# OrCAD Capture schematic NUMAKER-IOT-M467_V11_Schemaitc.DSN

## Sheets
1 Nu-Link2-Me: size A3; title: Nu-Link2-Me; rev: 1.0; company: CMHuang; note: Nu-Link2-Me
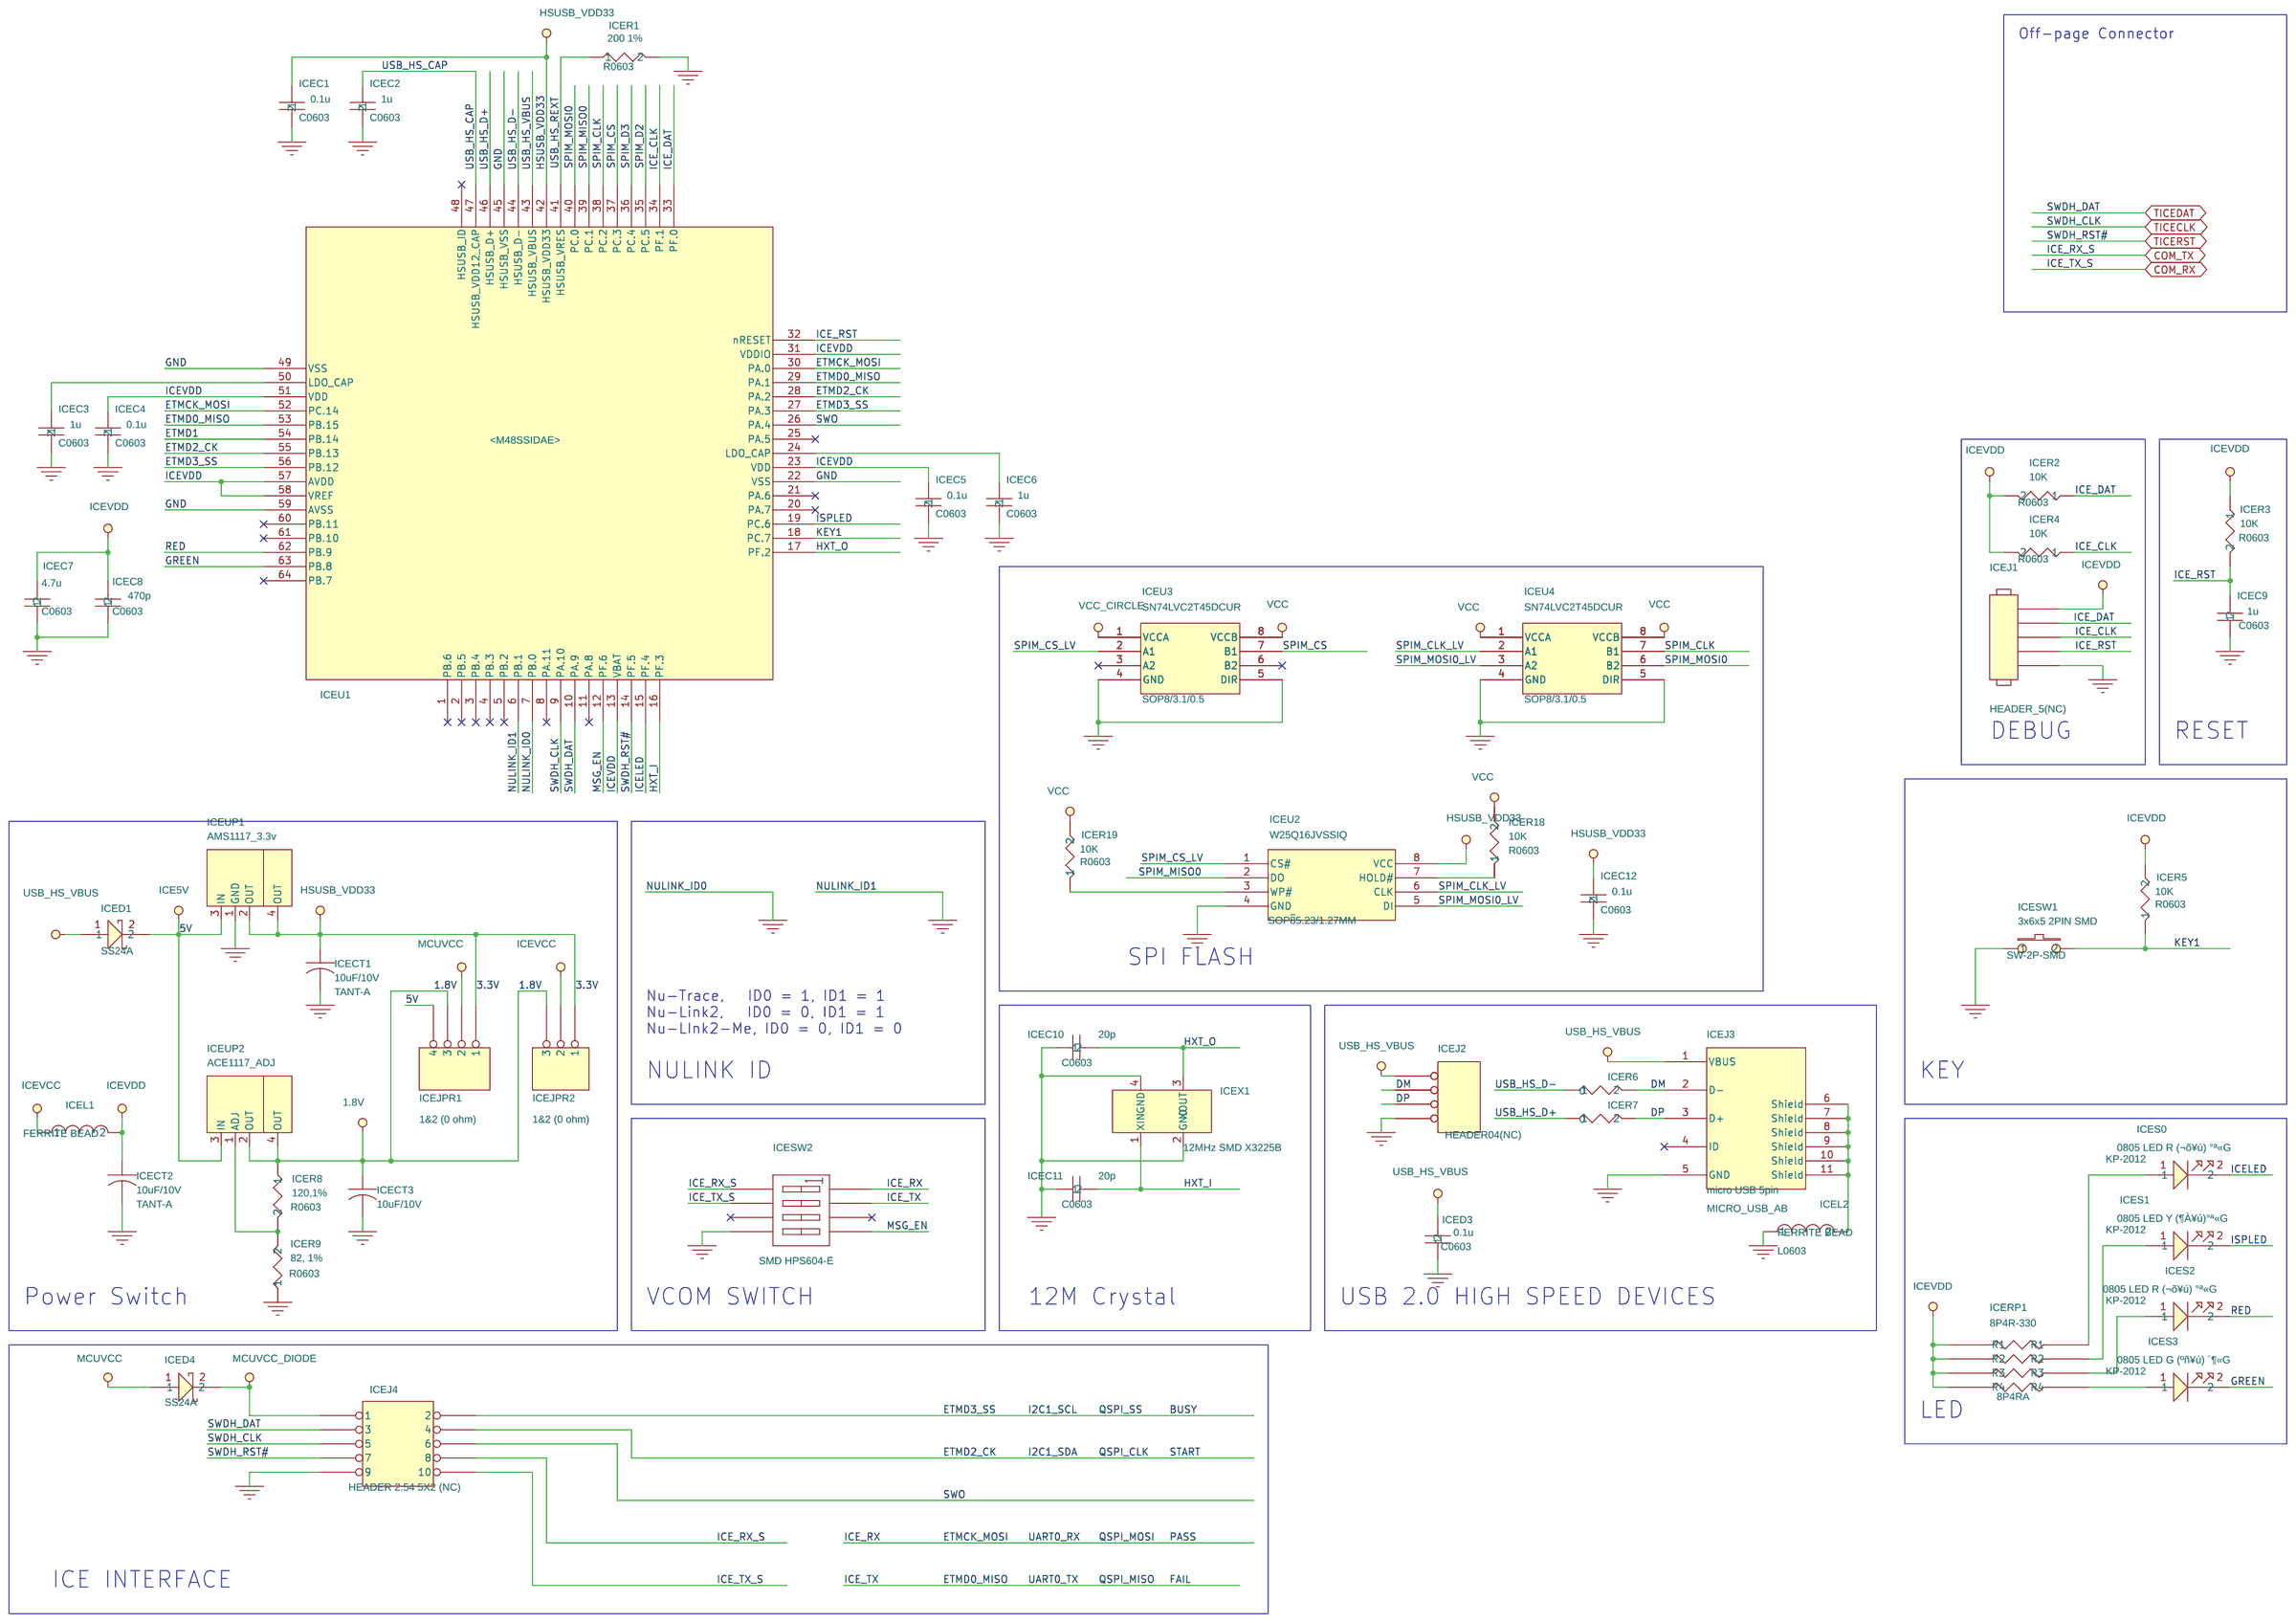
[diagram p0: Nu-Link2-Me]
2 Power Source: size A; title: Power Source; rev: r1.0; note: NuMaker-IoT-M467
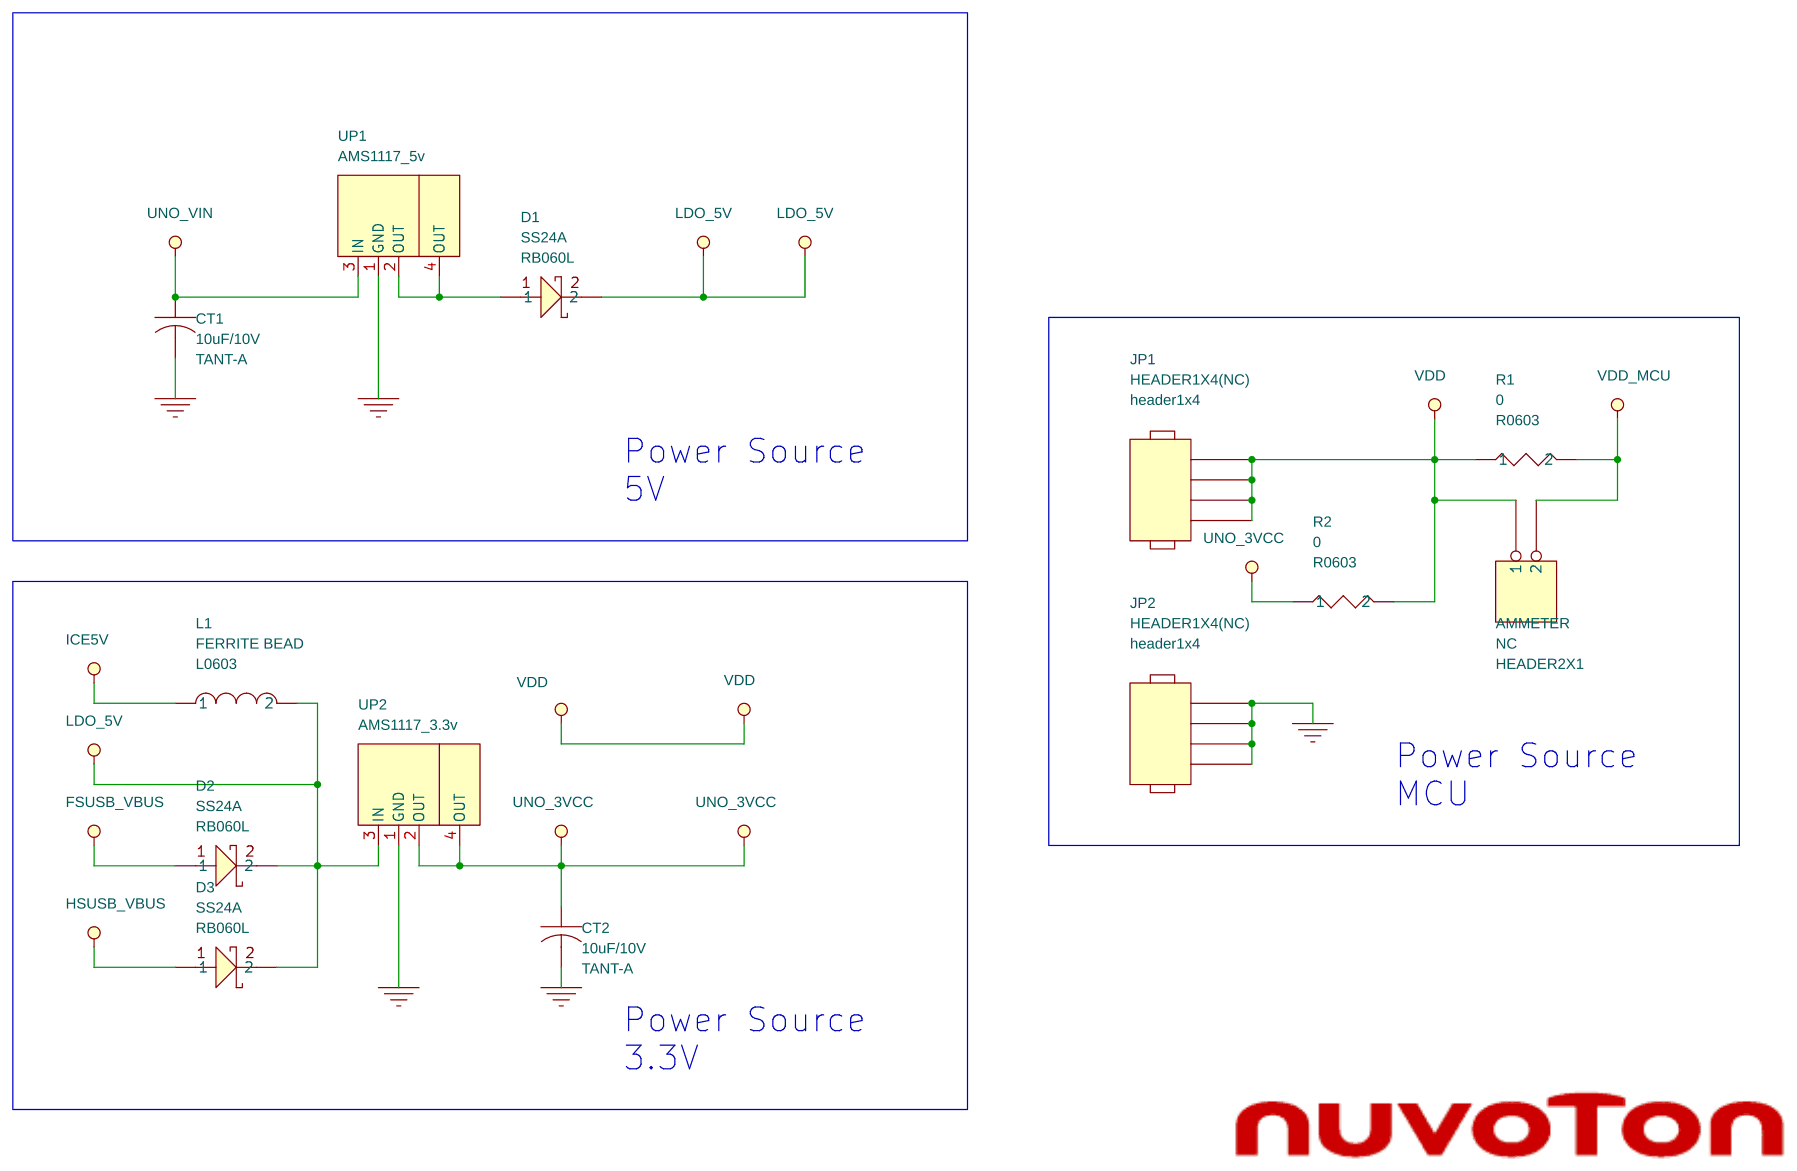
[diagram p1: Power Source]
3 M460_LQFP176: size C; title: M460_LQFP176; rev: r1.1; note: NuMaker-IoT-M467
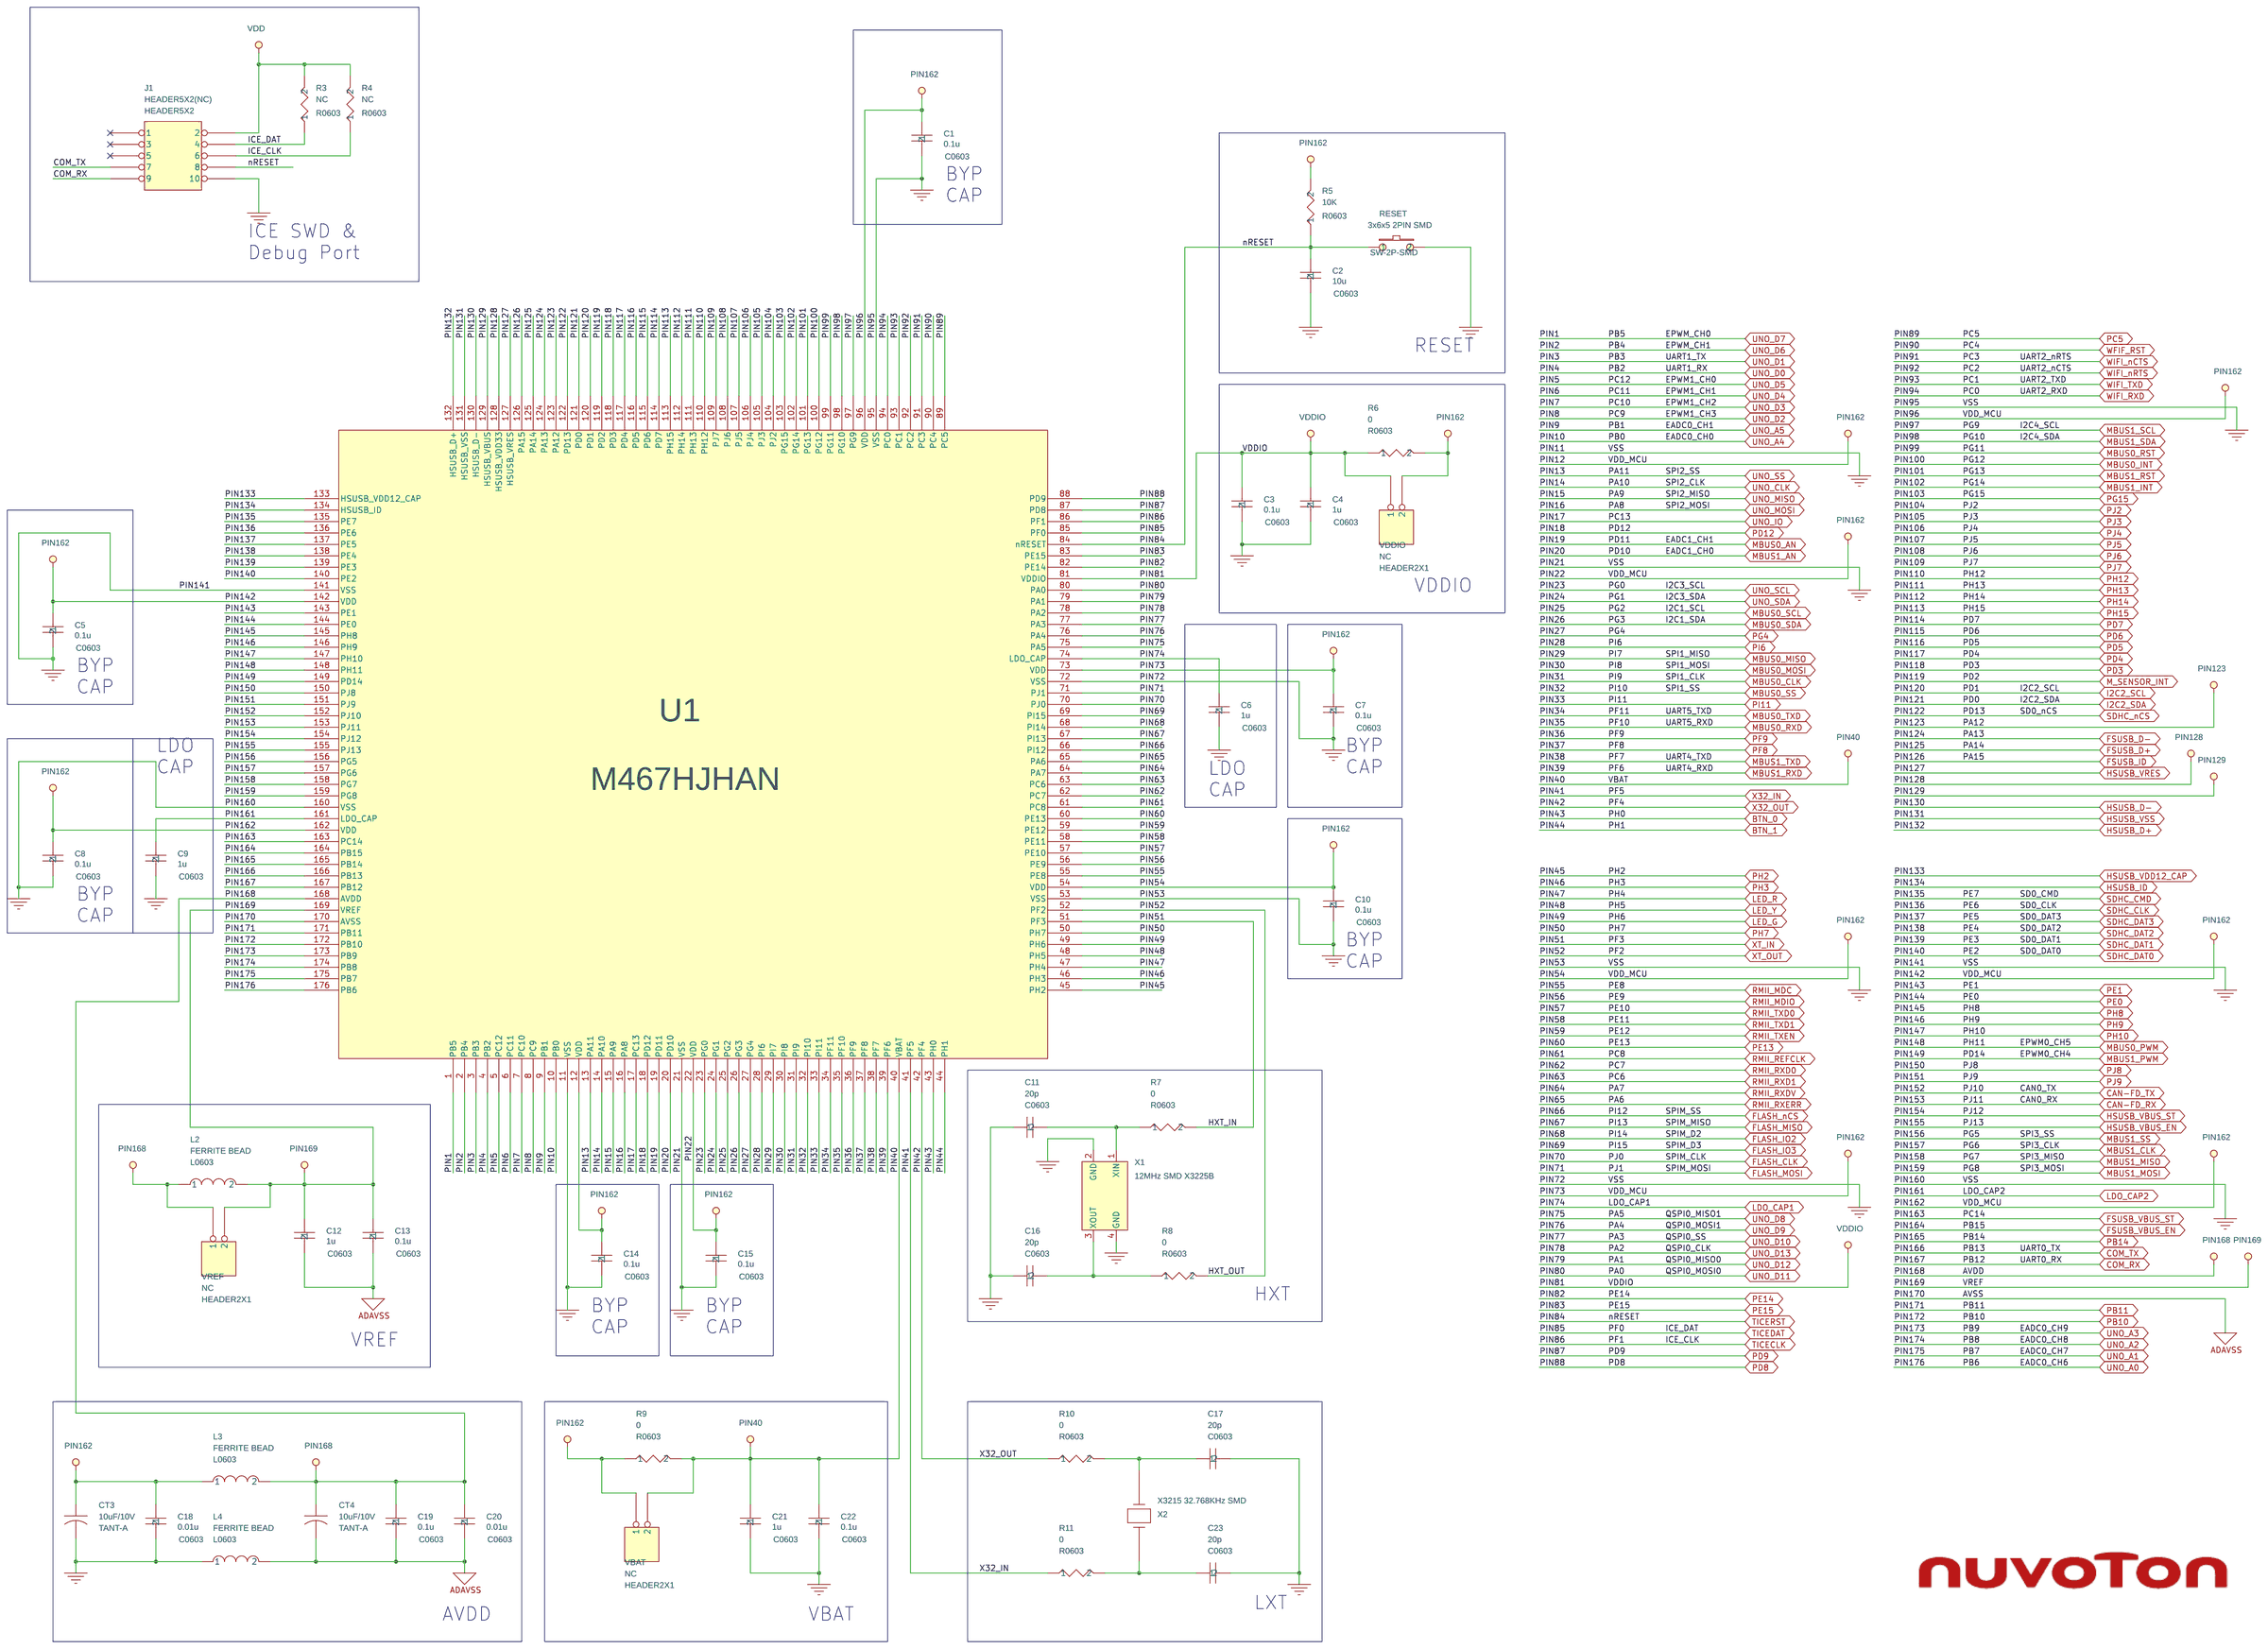
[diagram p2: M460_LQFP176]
4 SPI Flash: size A; title: SPI Flash; rev: r1.0; note: NuMaker-IoT-M467
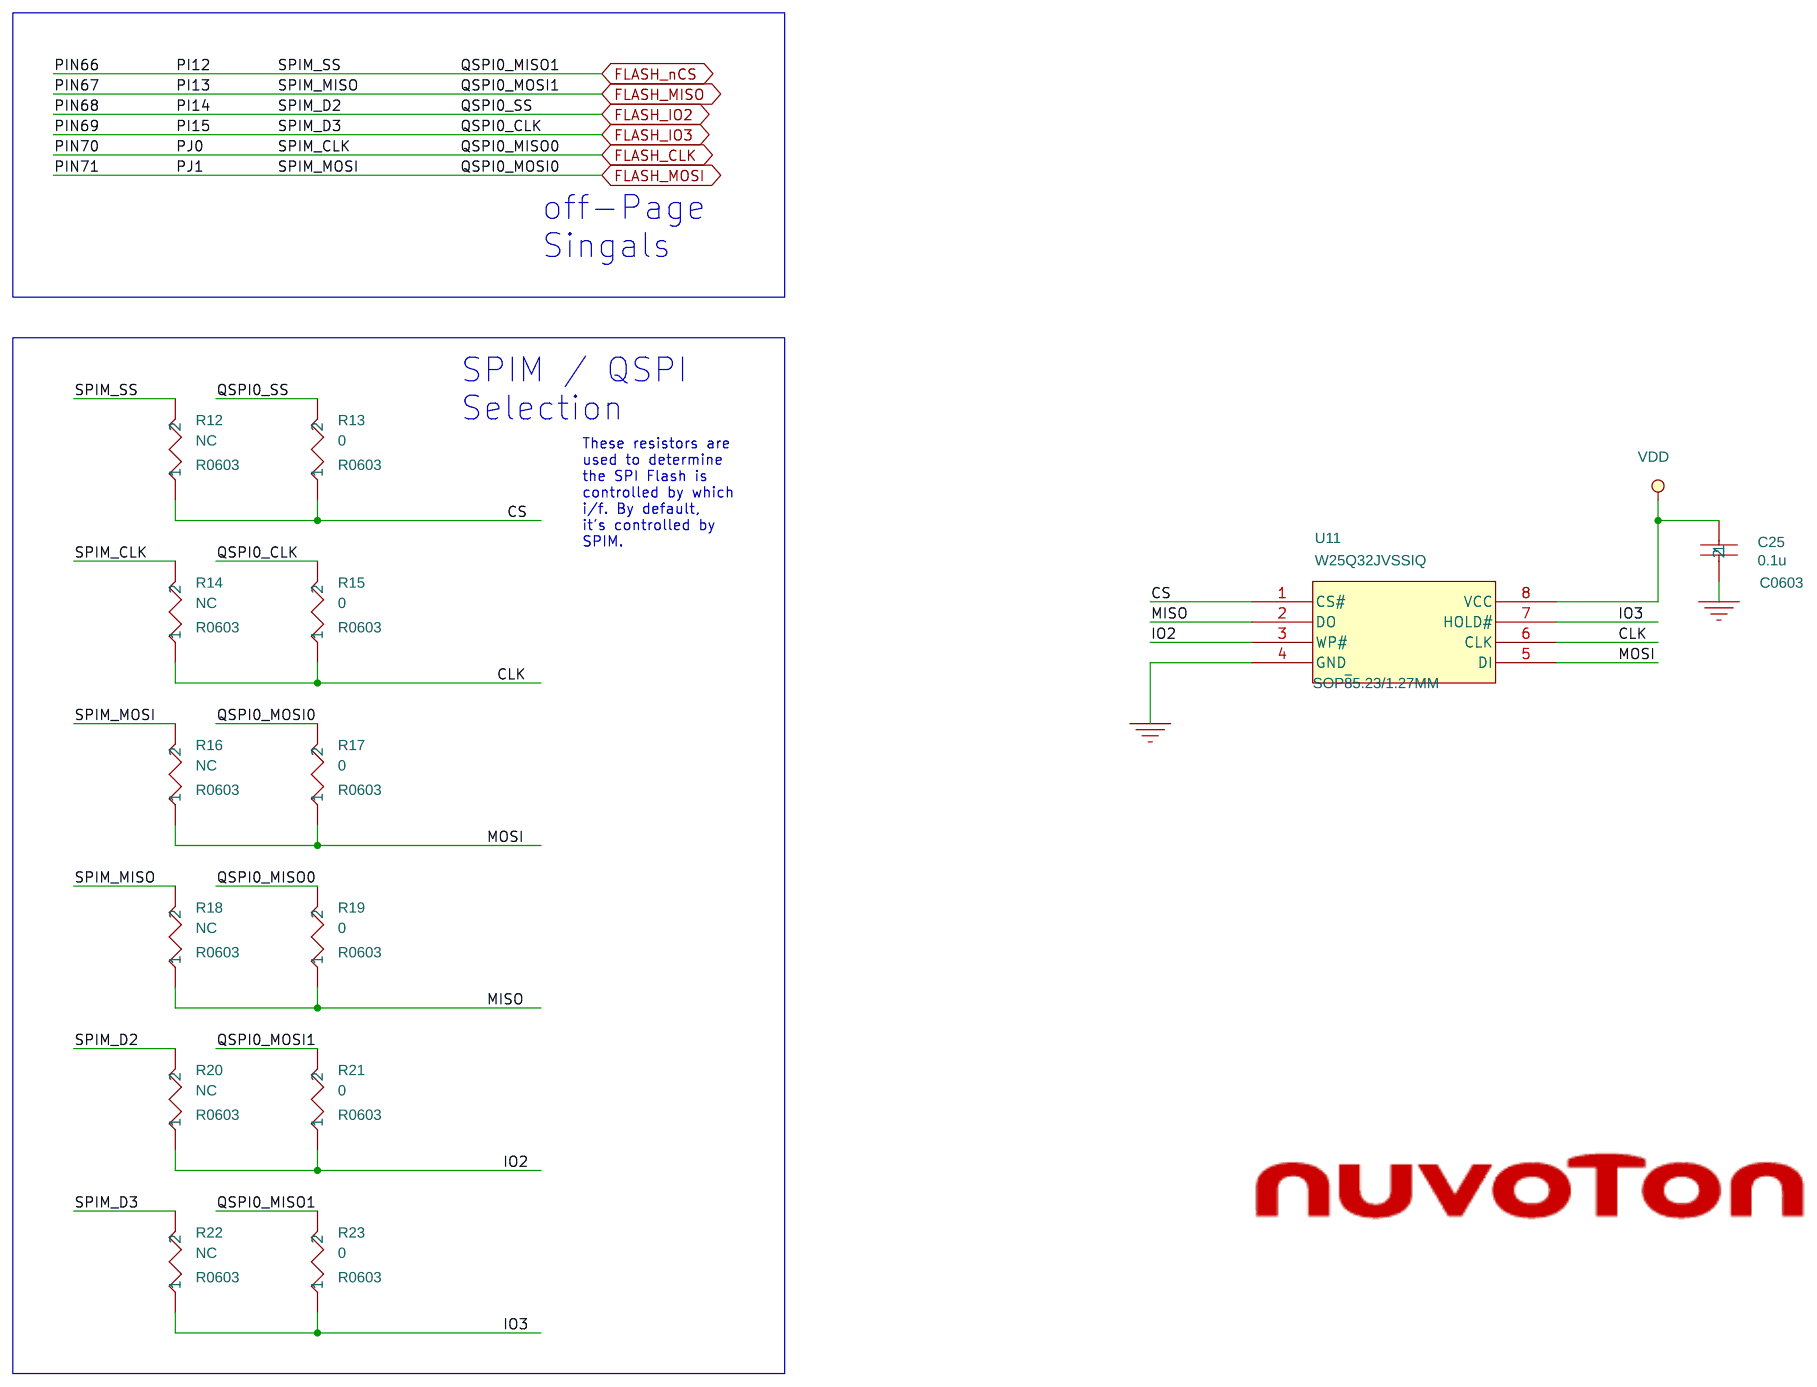
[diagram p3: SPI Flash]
5 FS-USB: size A; title: FS-USB; rev: r1.0; note: NuMaker-IoT-M467
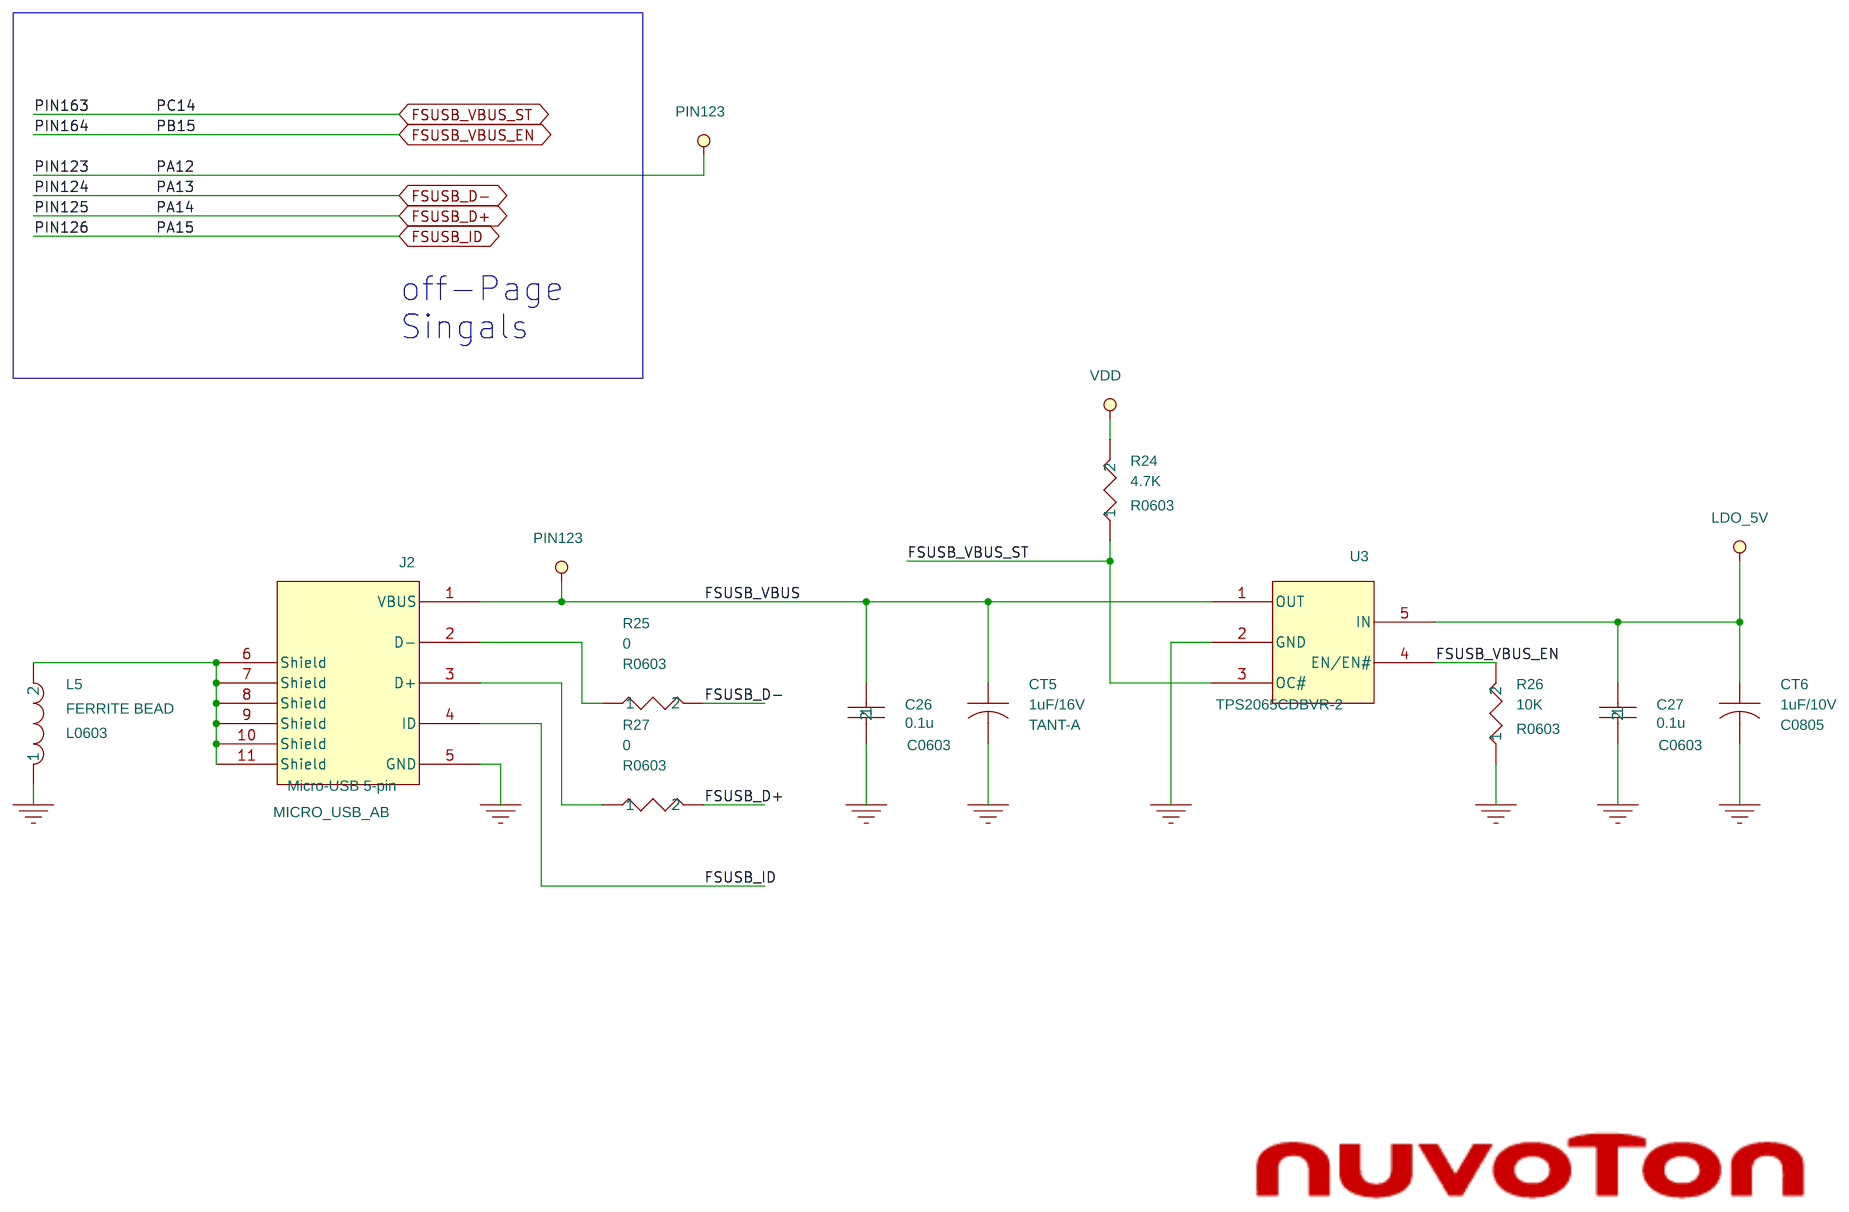
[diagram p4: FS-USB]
6 HS-USB: size A; title: HS-USB; rev: r1.0; note: NuMaker-IoT-M467
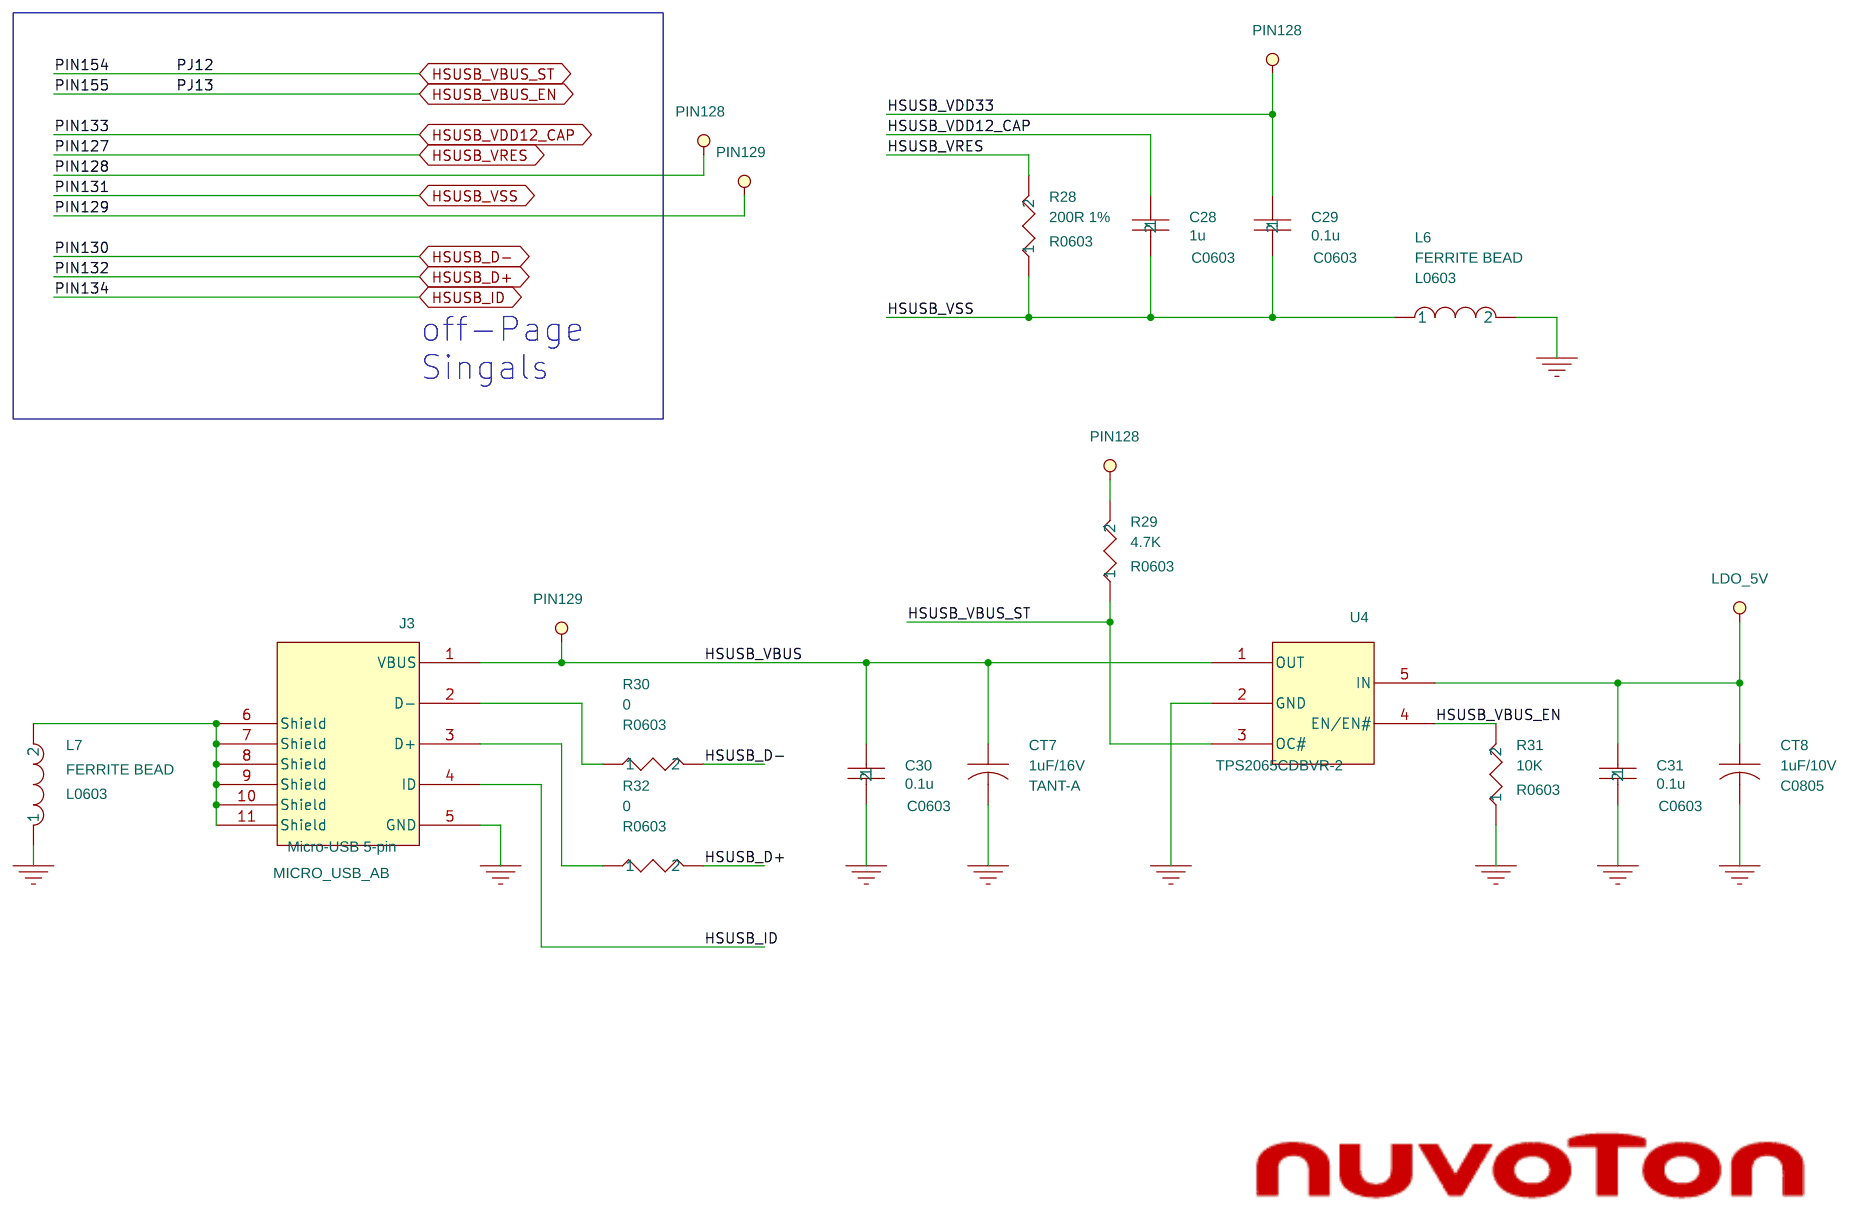
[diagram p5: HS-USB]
7 SD Card: size A; title: SD Card; rev: r1.0; note: NuMaker-IoT-M467
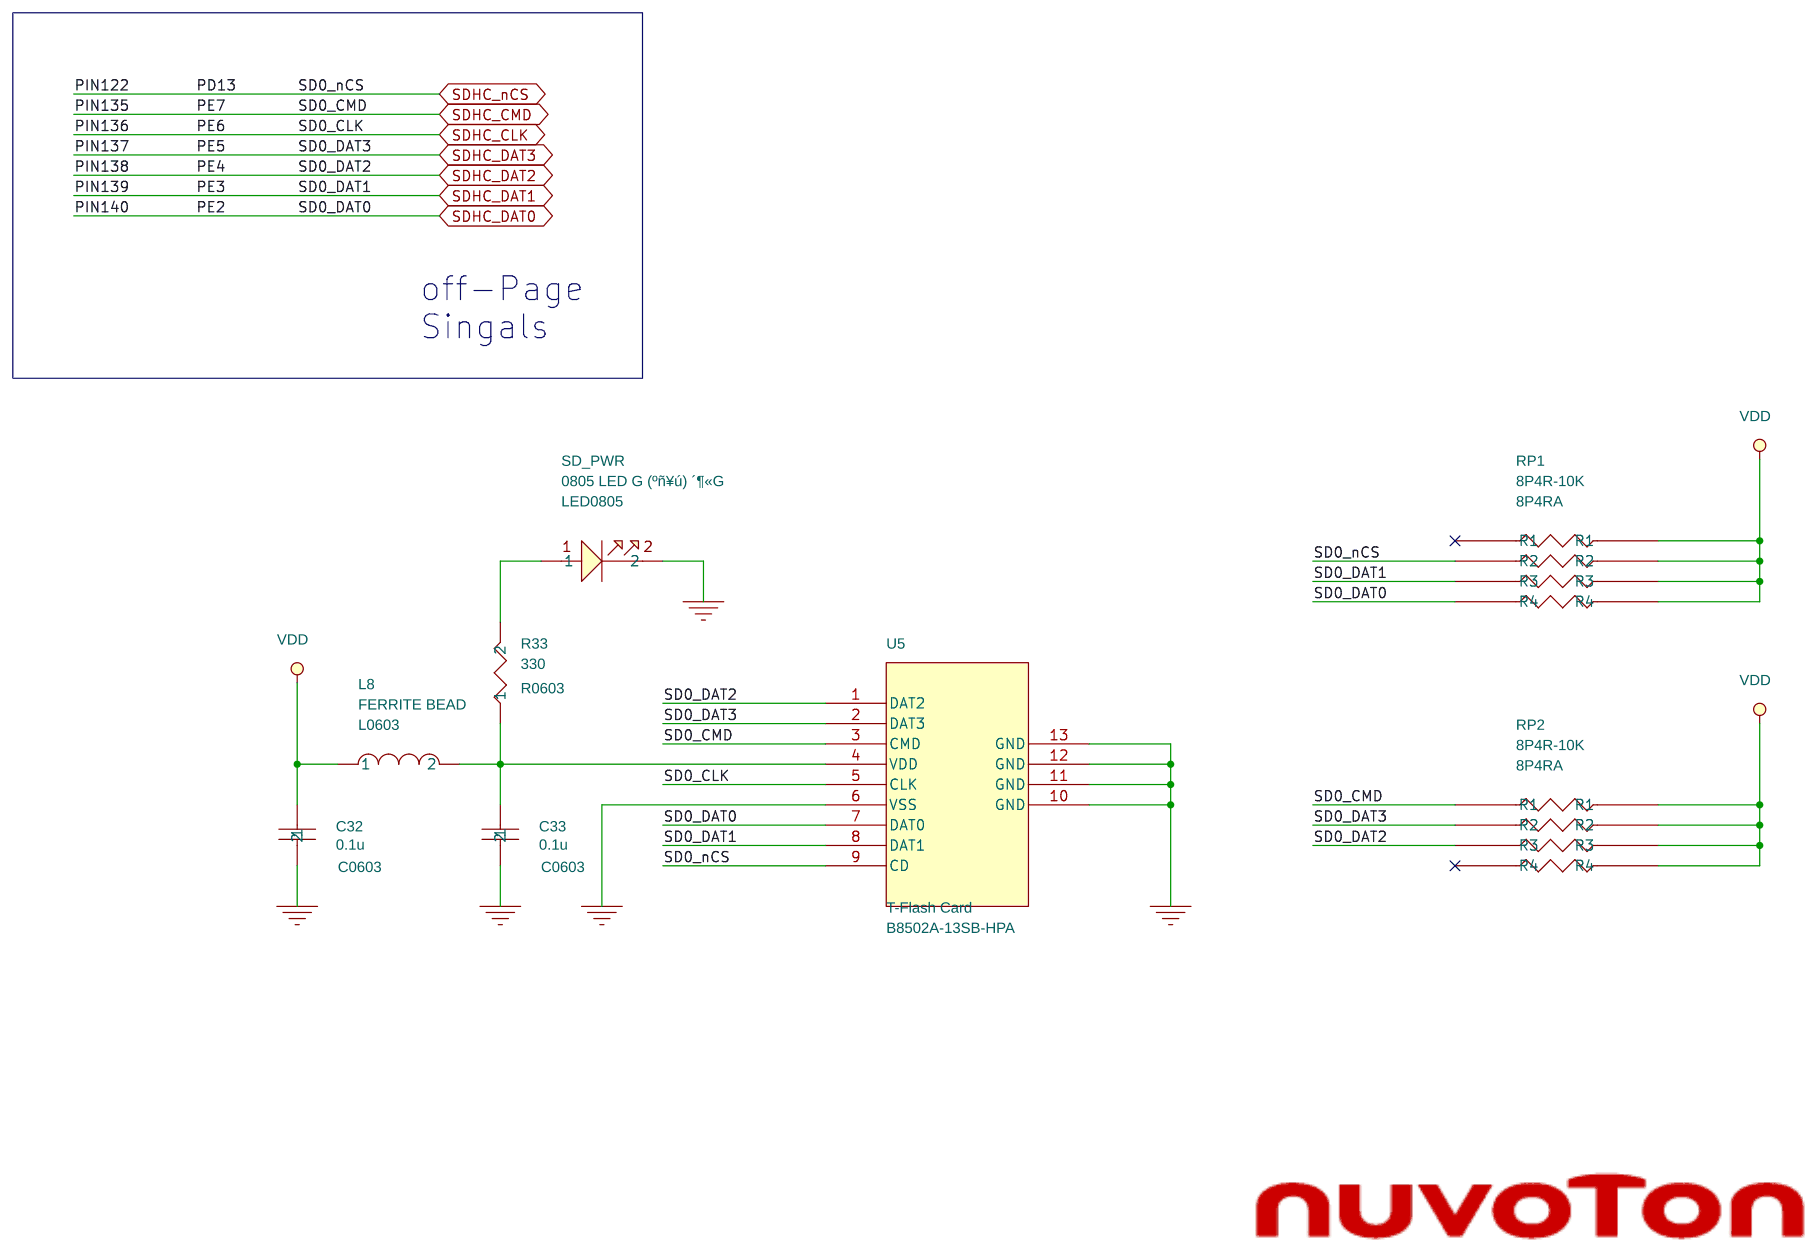
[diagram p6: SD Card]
8 UNO I/F: size A; title: UNO I/F; rev: r1.0; note: NuMaker-IoT-M467
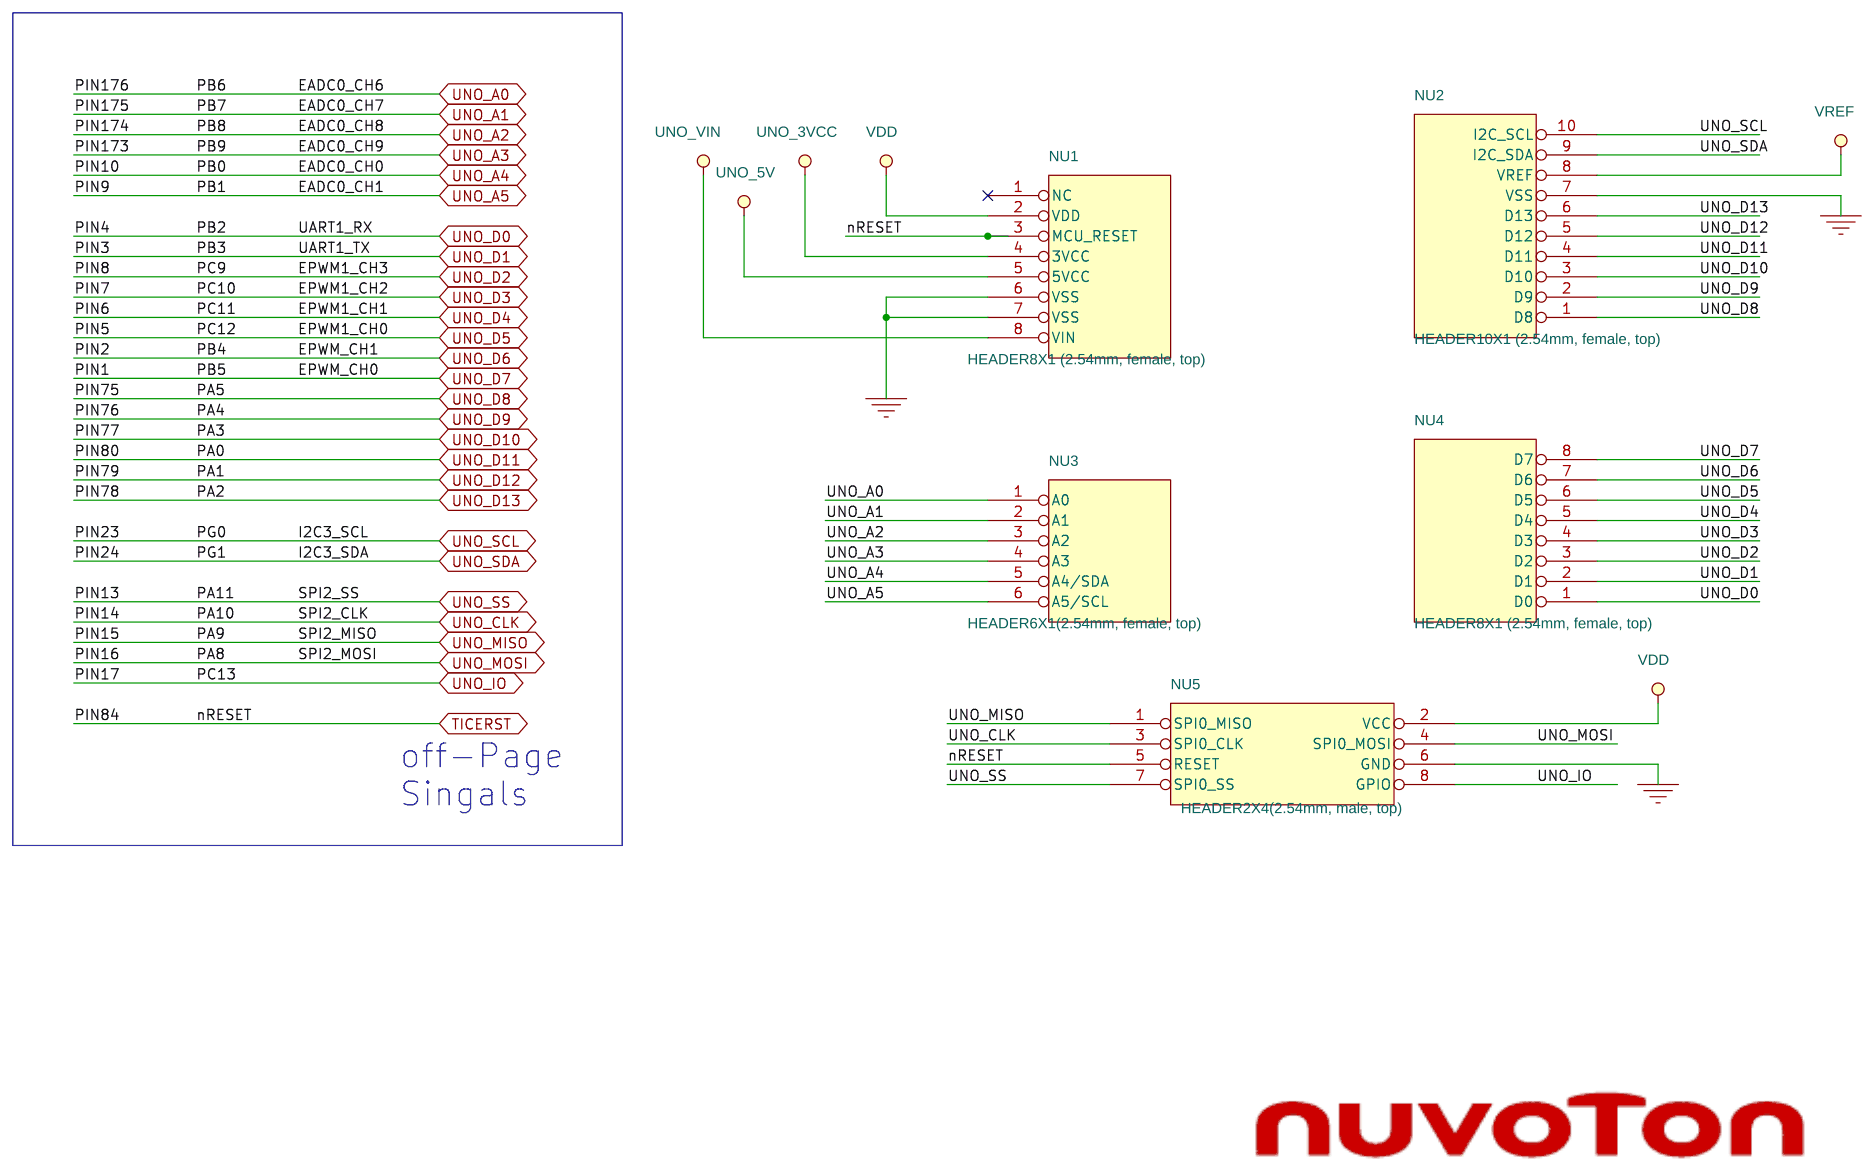
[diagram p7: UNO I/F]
9 Ethernet: size A; title: Ethernet PHY; rev: r1.0; note: NuMaker-IoT-M467
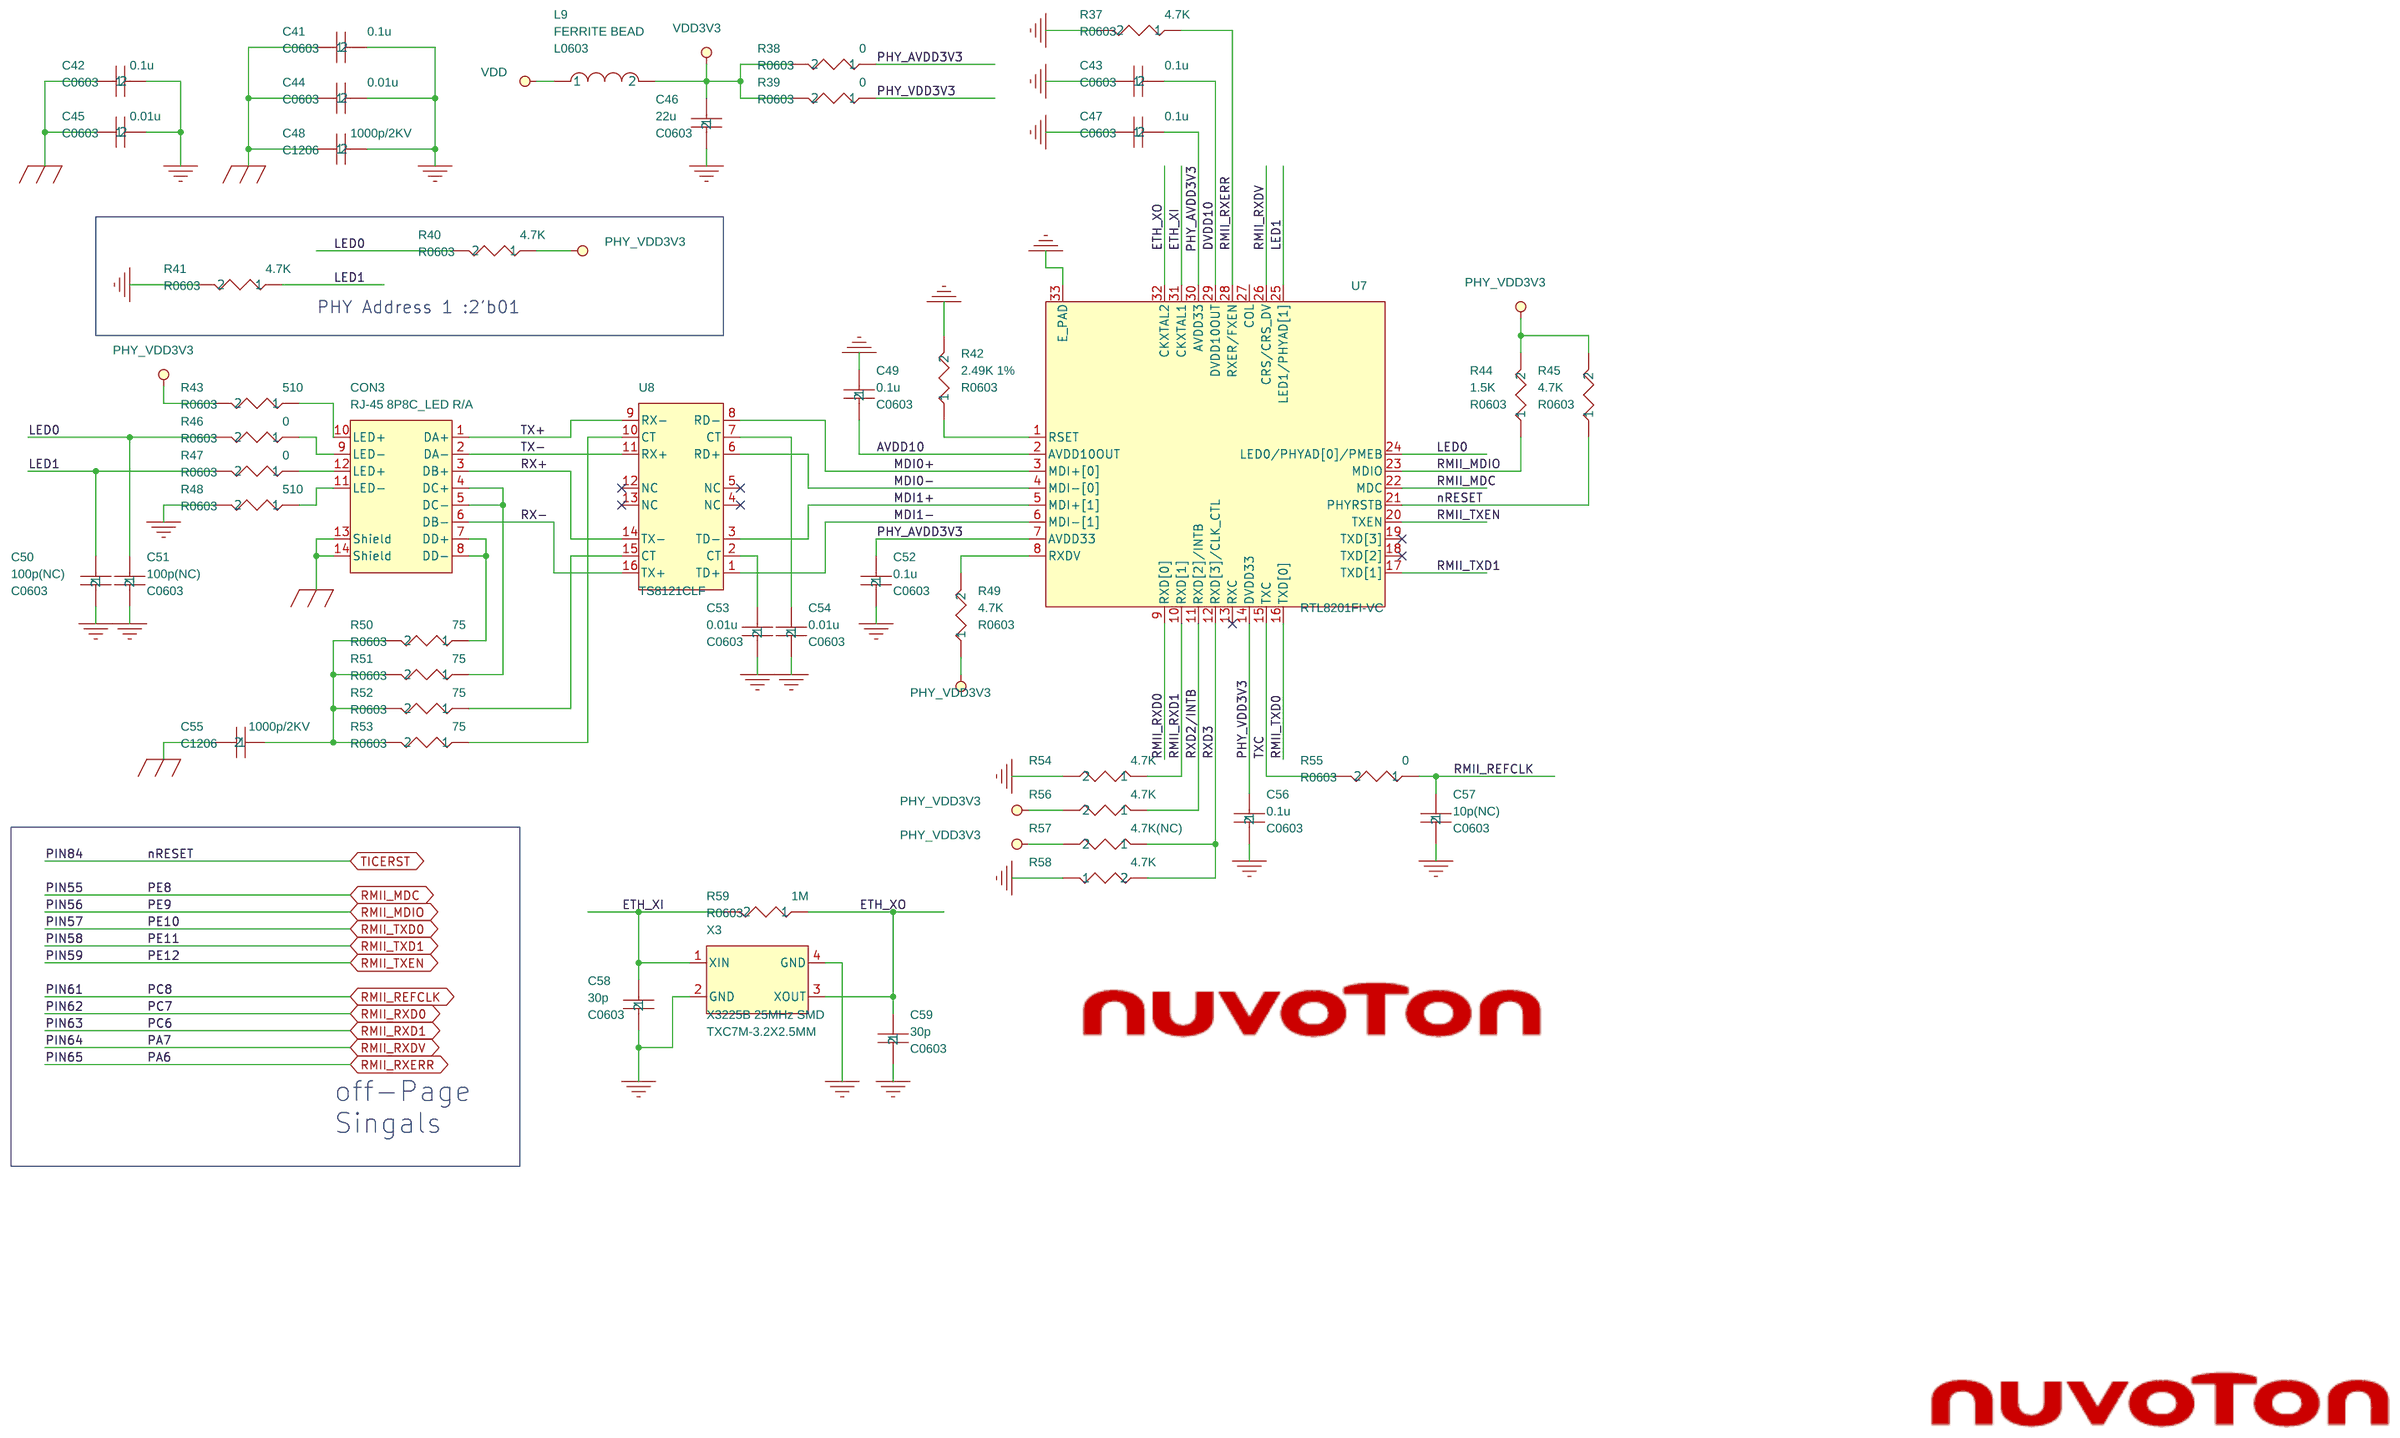
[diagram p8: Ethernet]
10 Thermal Sensor: size A; title: Thermal Sensor; rev: r1.0; note: NuMaker-IoT-M467
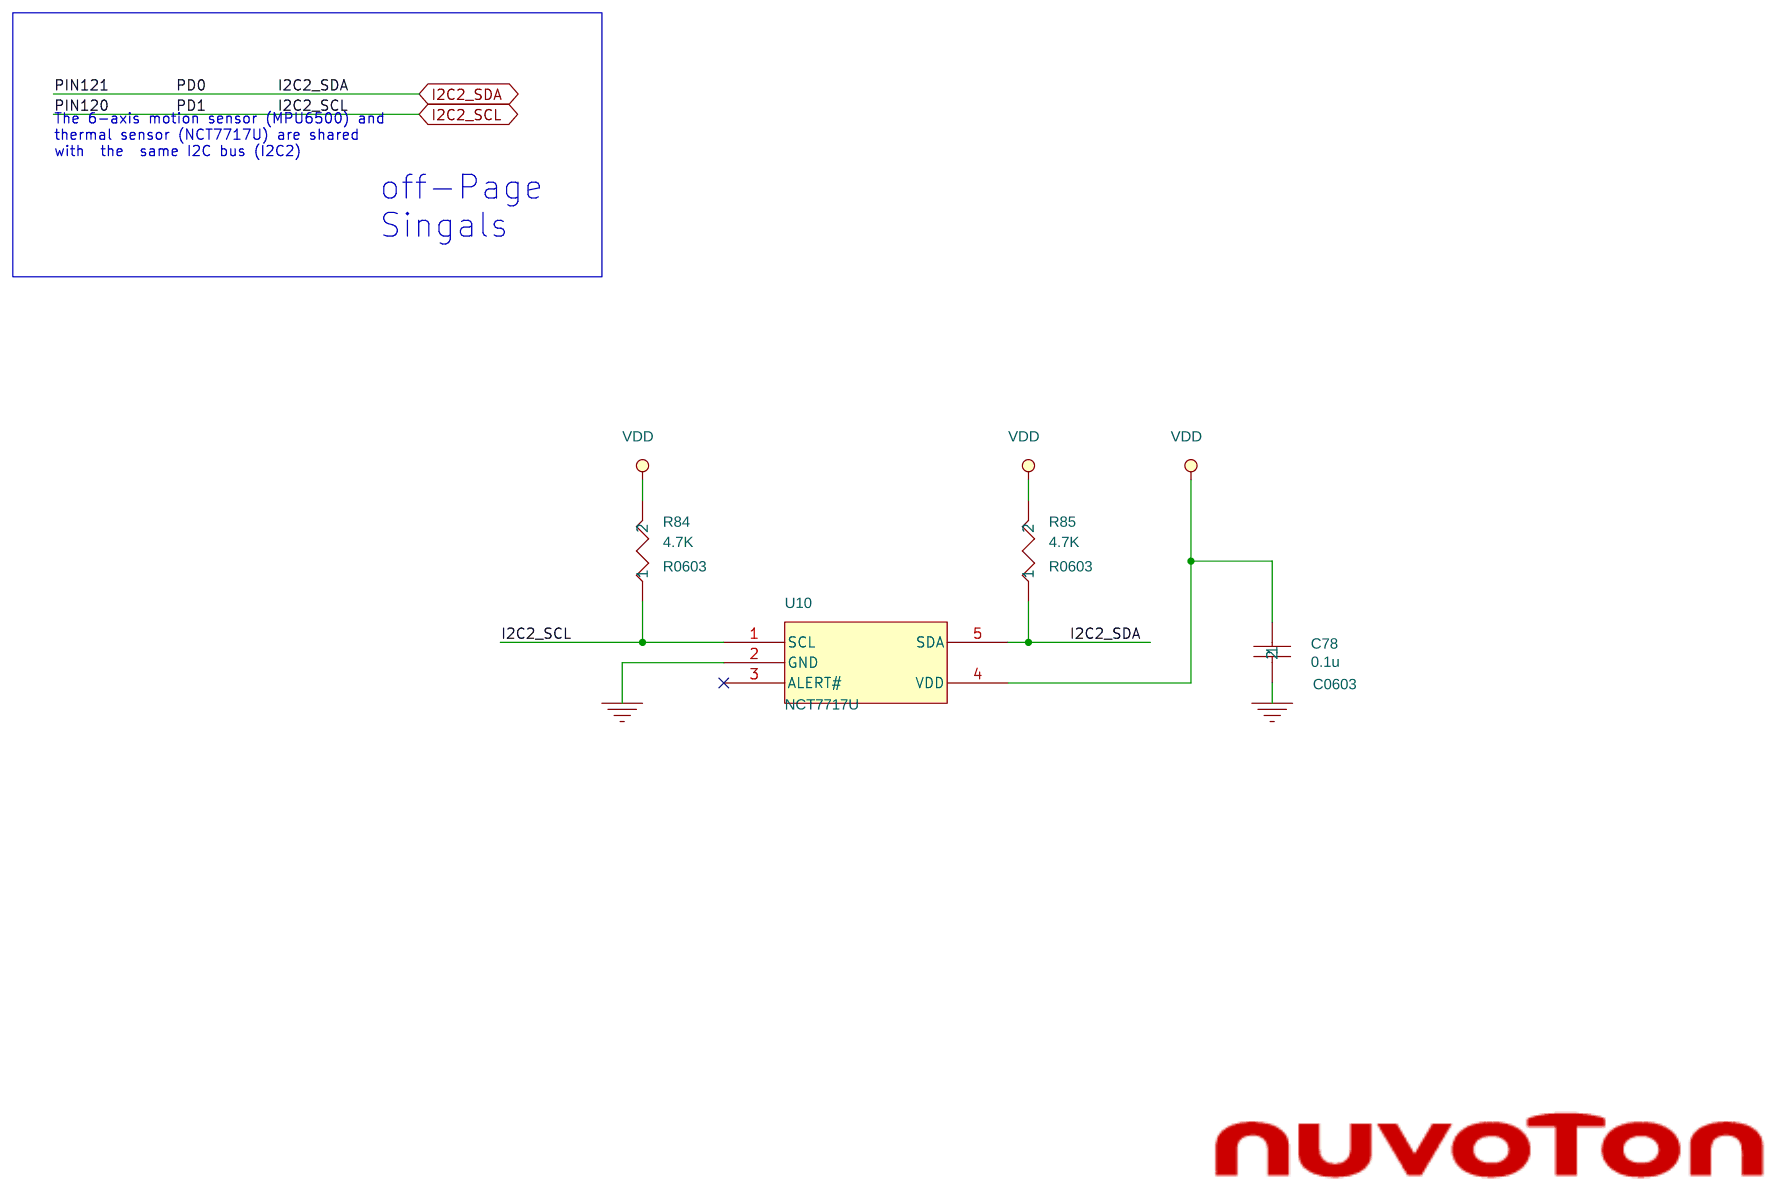
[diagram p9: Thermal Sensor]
11 Leds & Buttons: size A; title: Leds and Buttons; rev: r1.0; note: NuMaker-IoT-M467
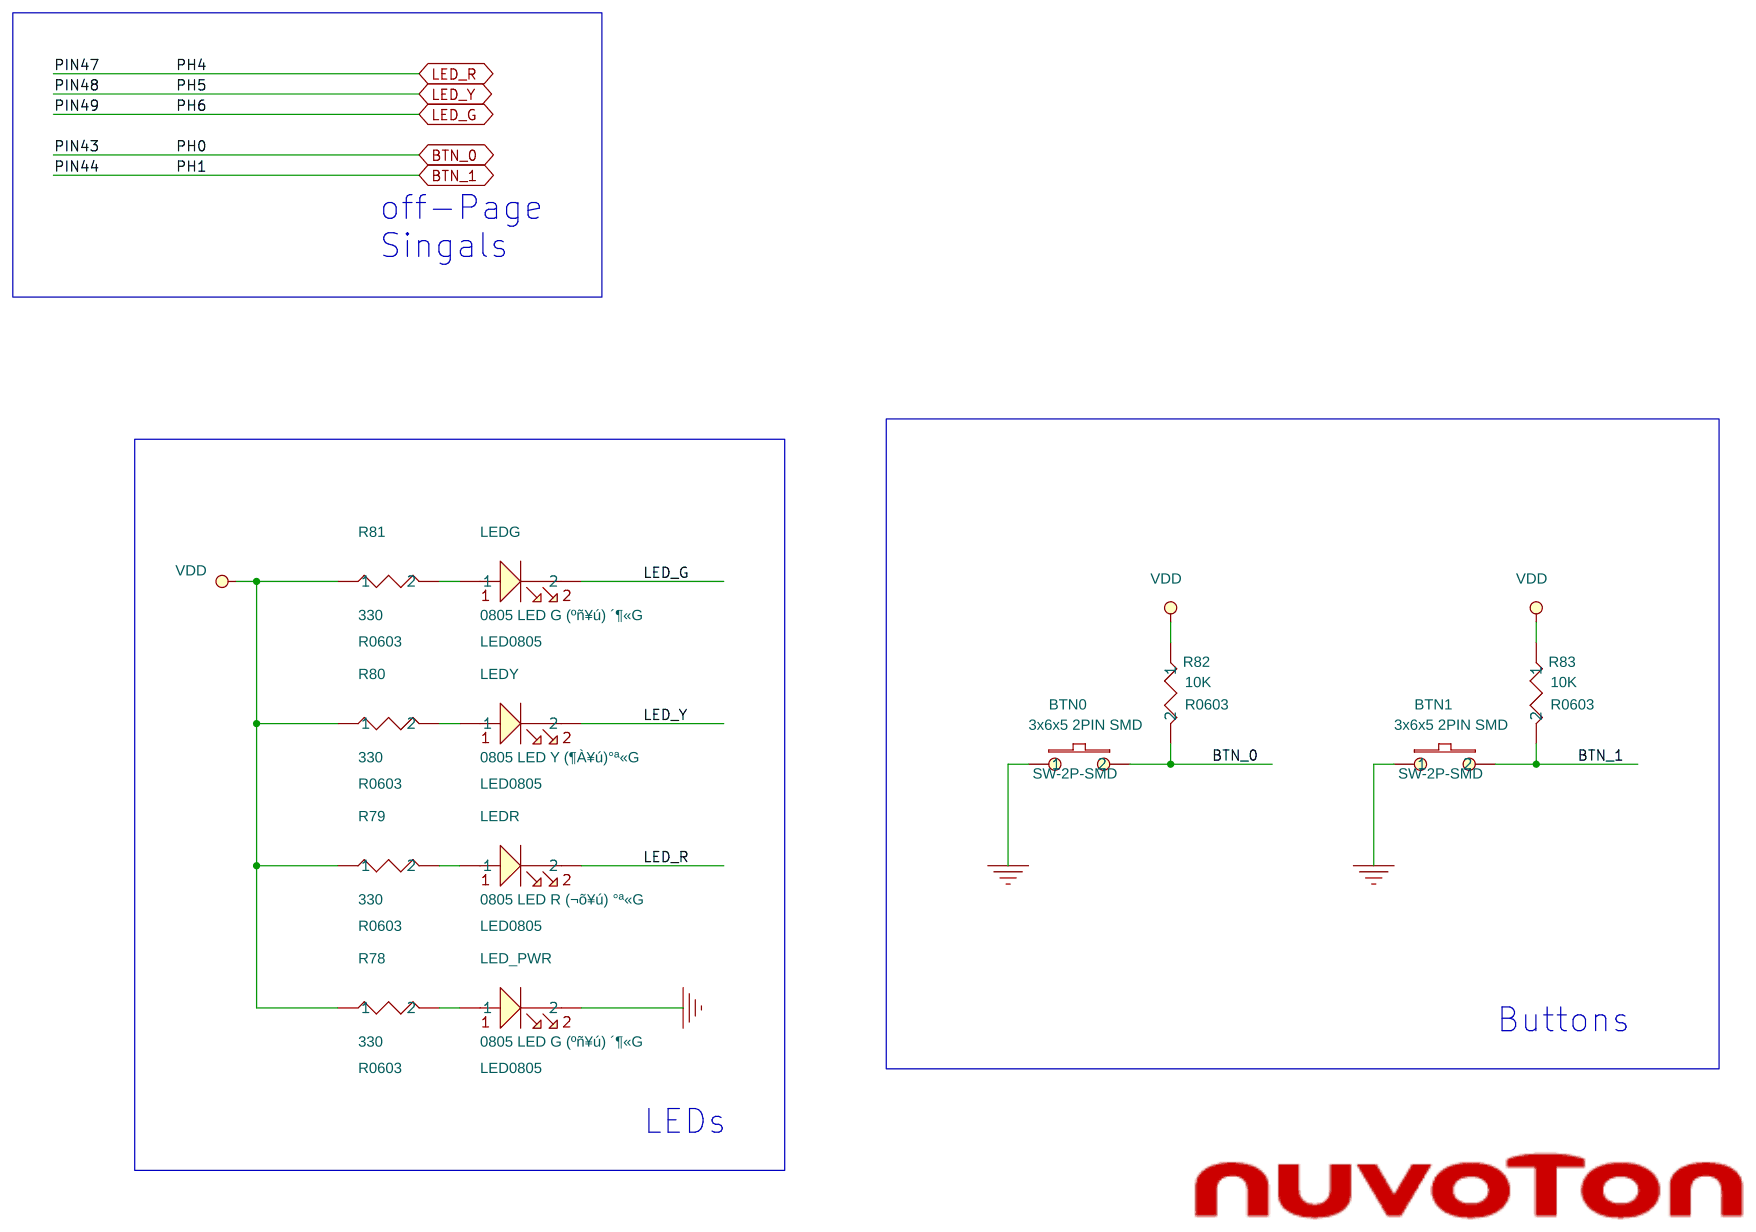
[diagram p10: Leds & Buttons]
12 WiFi Module: size A; title: WiFi; rev: r1.1; note: NuMaker-IoT-M467
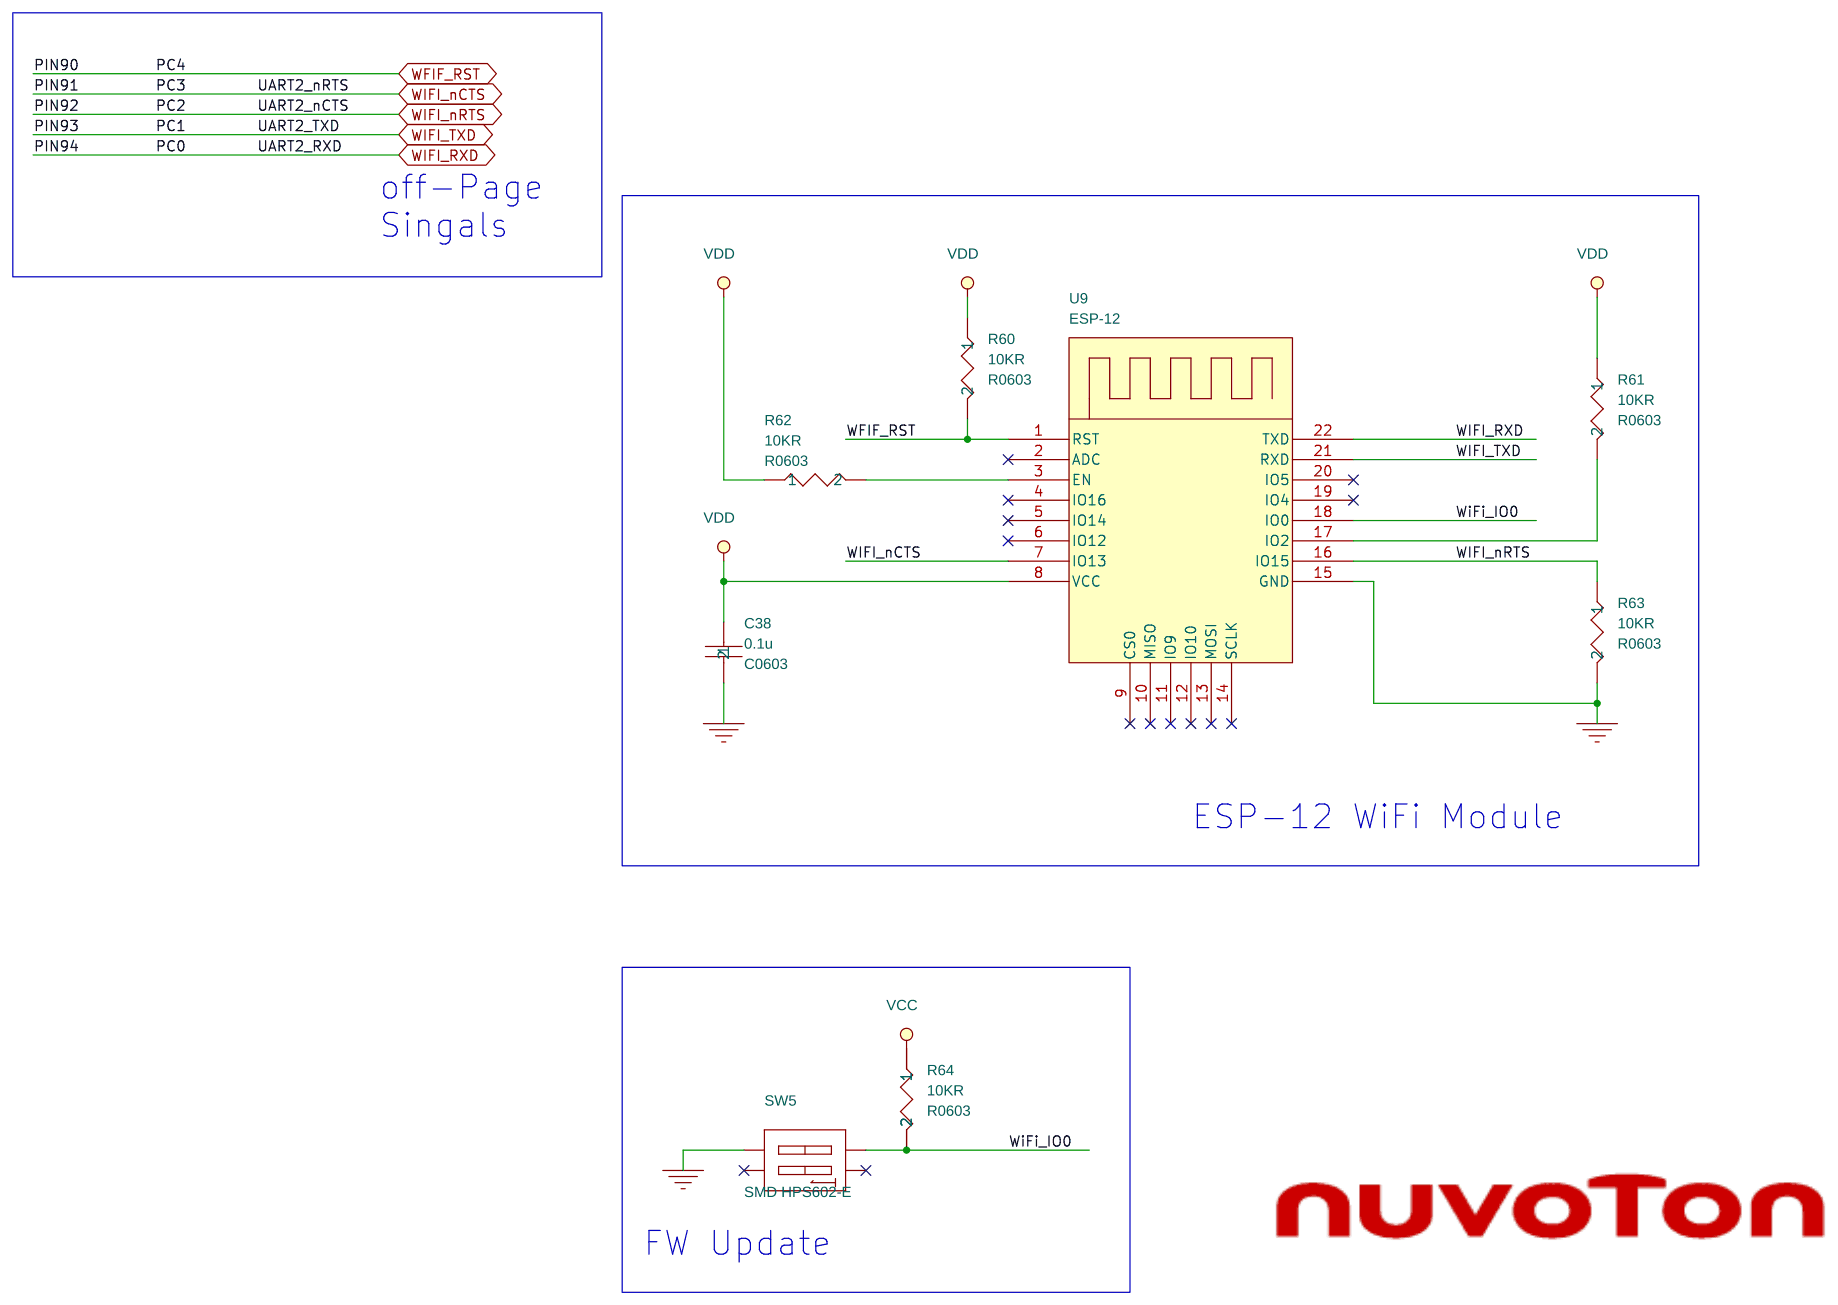
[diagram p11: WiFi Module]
13 MikroBUS: size A; title: MikroBUS; rev: r1.0; note: NuMaker-IoT-M467
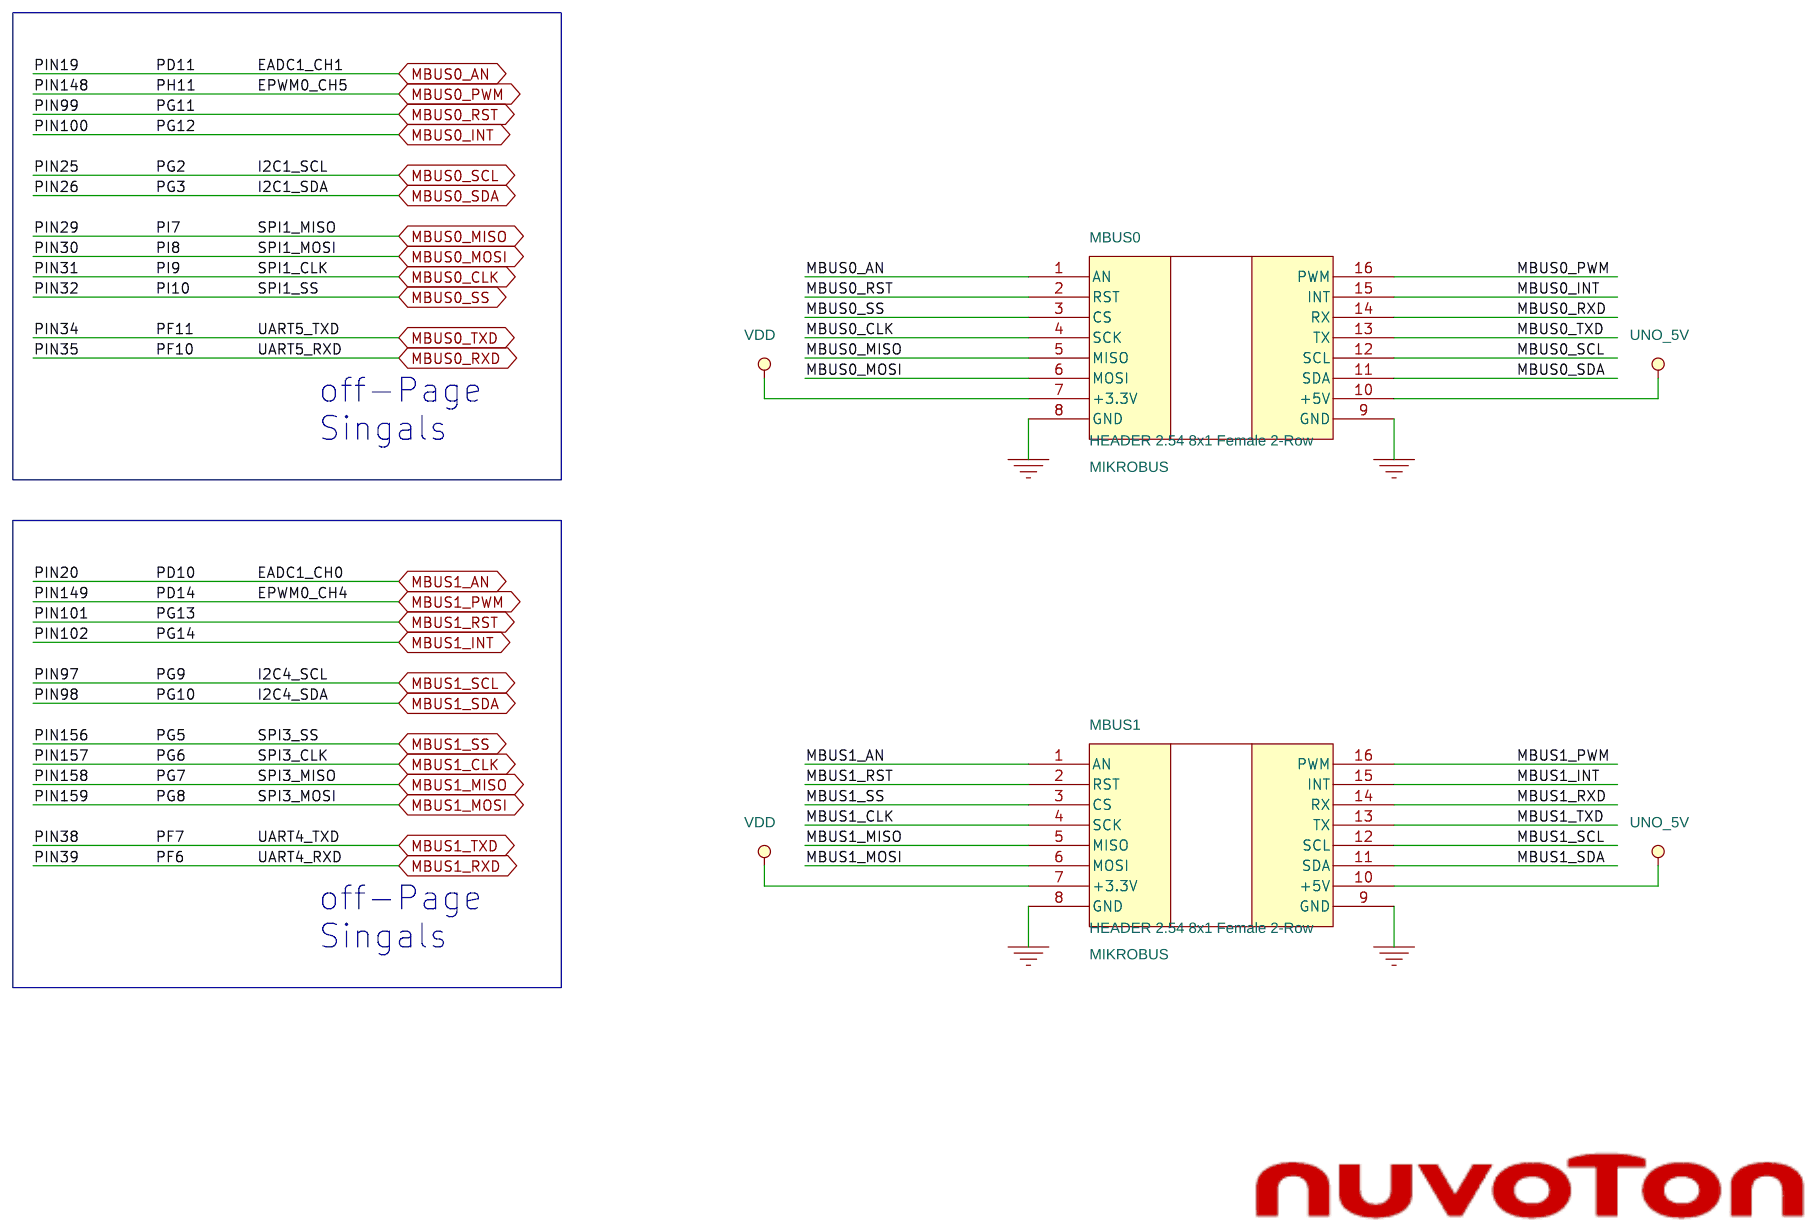
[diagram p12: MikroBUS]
14 CAN FD: size A; title: CAN-FD; rev: r1.0; note: NuMaker-IoT-M467
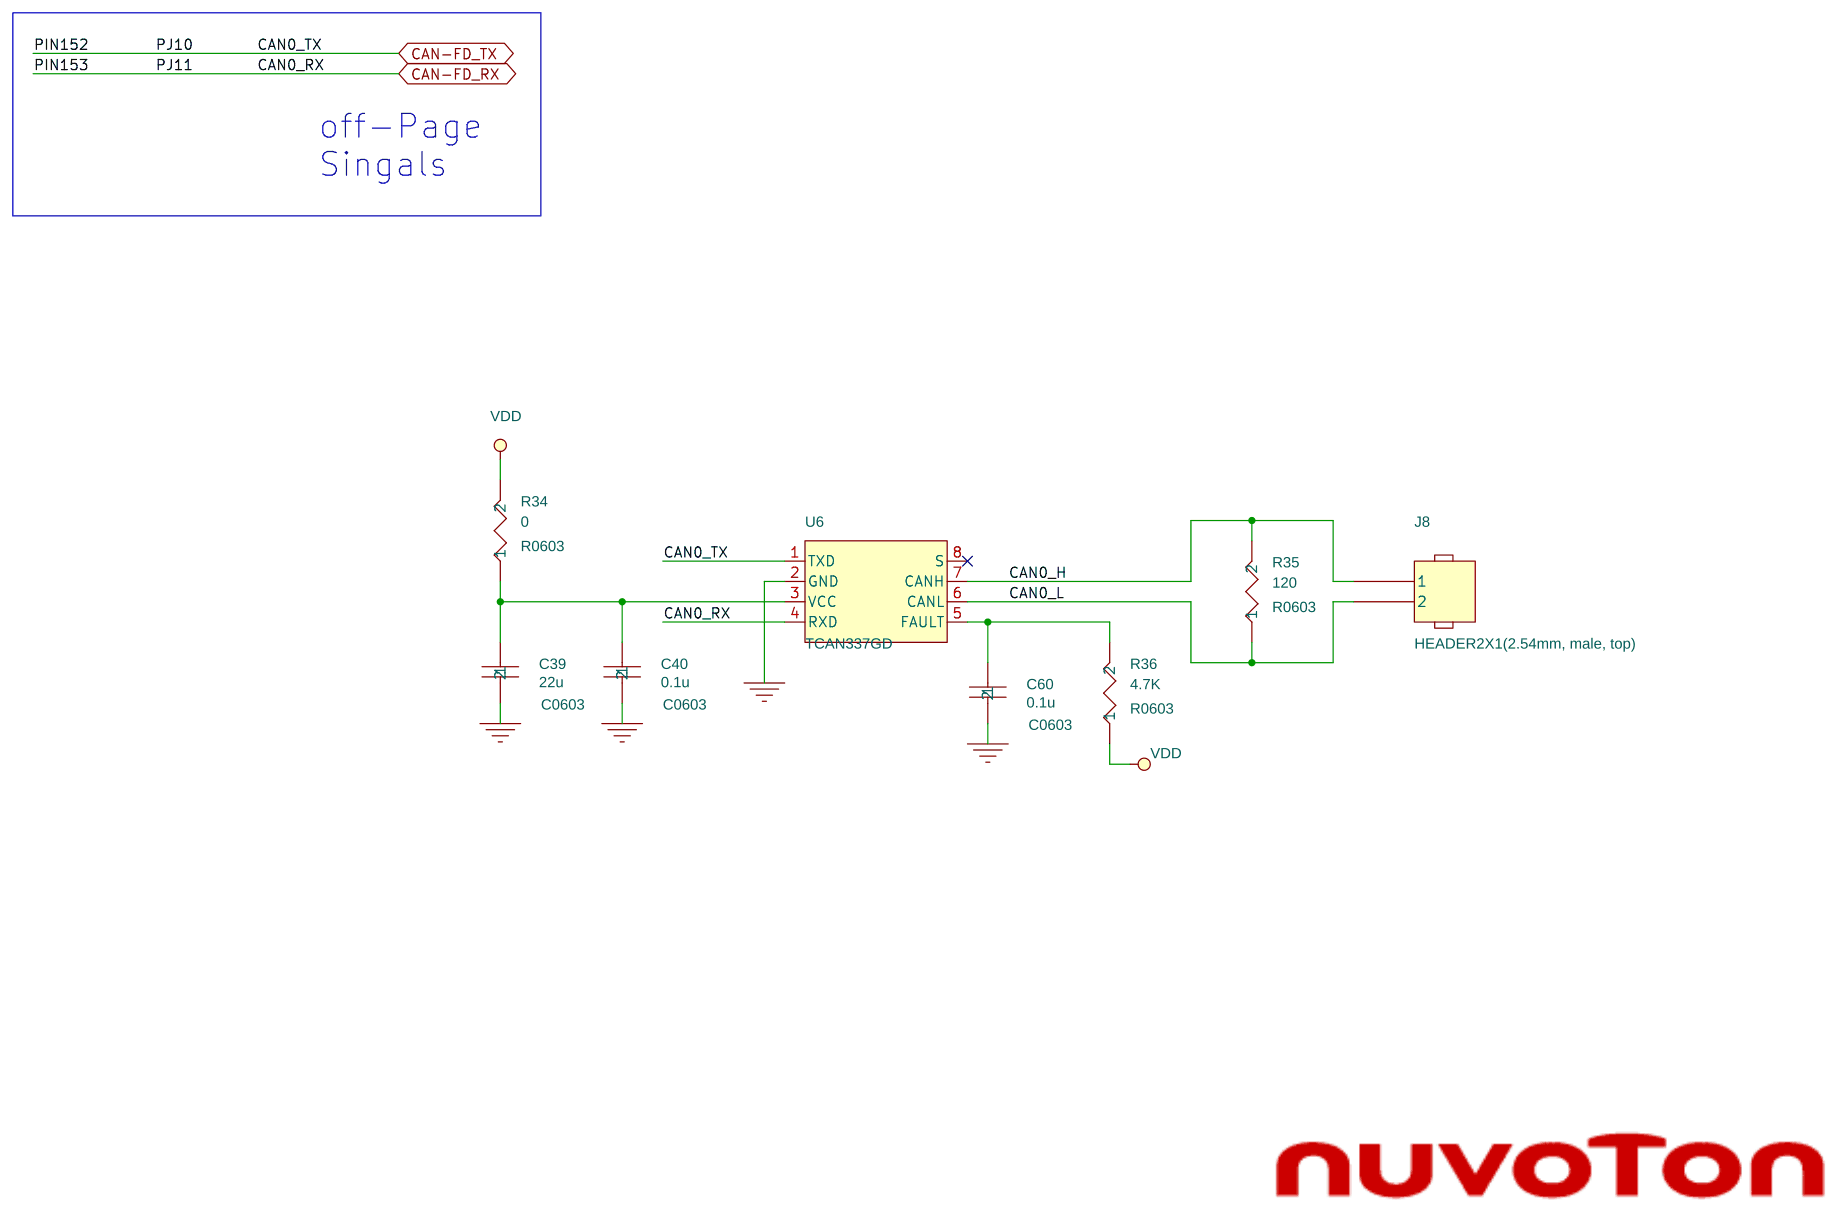
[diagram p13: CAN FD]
15 6-Axis Motion Sensor: size A; title: 6-Axis Motion Sensor; rev: r1.0; note: NuMaker-IoT-M467
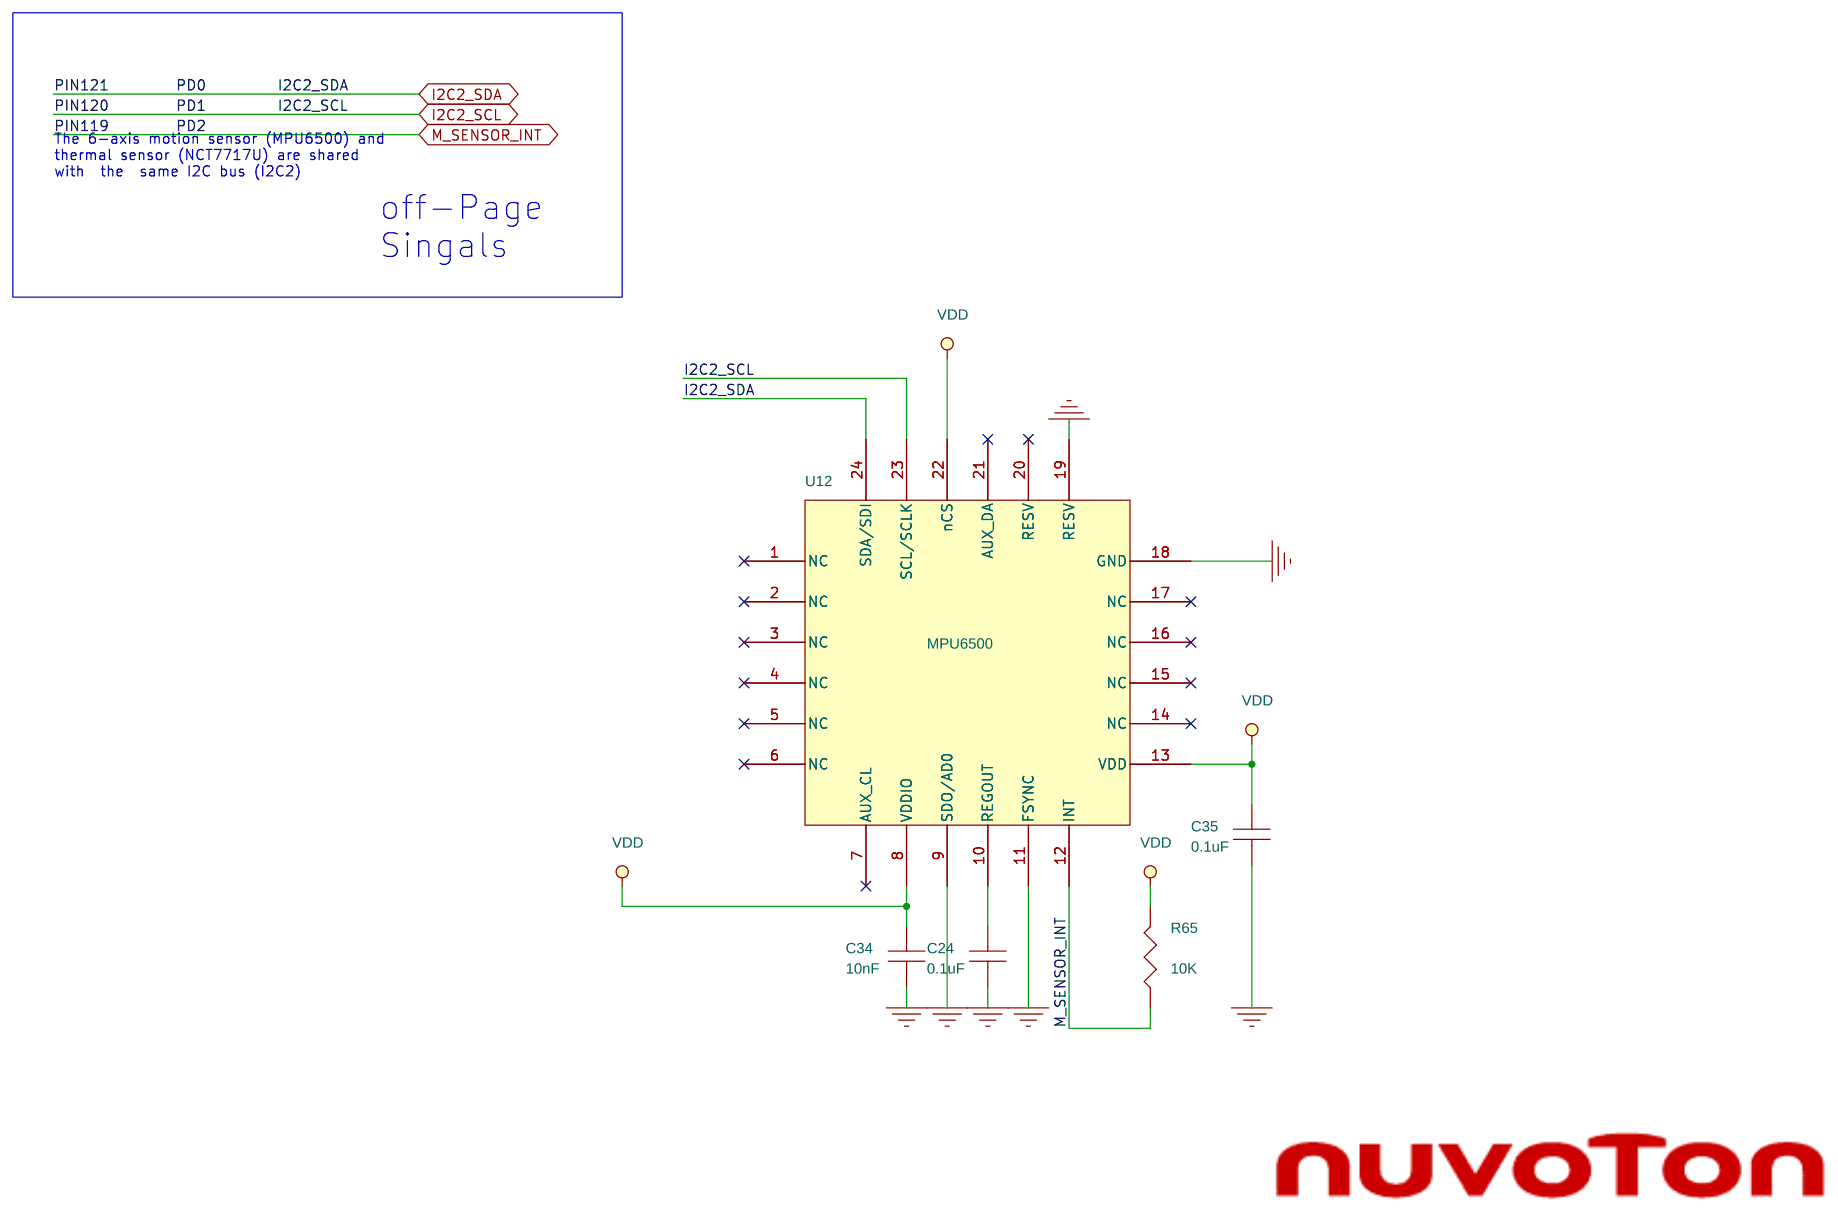
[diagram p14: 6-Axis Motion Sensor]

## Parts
sheet 6-Axis Motion Sensor
C24  0.1uF  [C0603]
C34  10nF  [C0603]
C35  0.1uF  [C0603]
R65  10K  [R0603]
U12  MPU6500  [QFN-24-3X3X0.9MM]
sheet CAN FD
C39  22u  [C0603]
C40  0.1u  [C0603]
C60  0.1u  [C0603]
J8  HEADER2X1(2.54mm, male, top)  [HEADER2x1]
R34  0  [R0603]
R35  120  [R0603]
R36  4.7K  [R0603]
U6  TCAN337GD  [SOIC8]
sheet Ethernet
C41  0.1u  [C0603]
C42  0.1u  [C0603]
C43  0.1u  [C0603]
C44  0.01u  [C0603]
C45  0.01u  [C0603]
C46  22u  [C0603]
C47  0.1u  [C0603]
C48  1000p/2KV  [C1206]
C49  0.1u  [C0603]
C50  100p(NC)  [C0603]
C51  100p(NC)  [C0603]
C52  0.1u  [C0603]
C53  0.01u  [C0603]
C54  0.01u  [C0603]
C55  1000p/2KV  [C1206]
C56  0.1u  [C0603]
C57  10p(NC)  [C0603]
C58  30p  [C0603]
C59  30p  [C0603]
CON3  RJ-45 8P8C_LED R/A  [RJ45\8P\JA\LED]
L9  FERRITE BEAD  [L0603]
R37  4.7K  [R0603]
R38  0  [R0603]
R39  0  [R0603]
R40  4.7K  [R0603]
R41  4.7K  [R0603]
R42  2.49K 1%  [R0603]
R43  510  [R0603]
R44  1.5K  [R0603]
R45  4.7K  [R0603]
R46  0  [R0603]
R47  0  [R0603]
R48  510  [R0603]
R49  4.7K  [R0603]
R50  75  [R0603]
R51  75  [R0603]
R52  75  [R0603]
R53  75  [R0603]
R54  4.7K  [R0603]
R55  0  [R0603]
R56  4.7K  [R0603]
R57  4.7K(NC)  [R0603]
R58  4.7K  [R0603]
R59  1M  [R0603]
U7  RTL8201FI-VC  [32-PIN-QFN]
U8  TS8121CLF  [ST6200T]
X3  X3225B 25MHz SMD  [TXC7M-3.2X2.5MM]
sheet FS-USB
C26  0.1u  [C0603]
C27  0.1u  [C0603]
CT5  1uF/16V  [TANT-A]
CT6  1uF/10V  [C0805]
J2  Micro-USB 5-pin  [MICRO_USB_AB]
L5  FERRITE BEAD  [L0603]
R24  4.7K  [R0603]
R25  0  [R0603]
R26  10K  [R0603]
R27  0  [R0603]
U3  TPS2065CDBVR-2  [SOT23-5]
sheet HS-USB
C28  1u  [C0603]
C29  0.1u  [C0603]
C30  0.1u  [C0603]
C31  0.1u  [C0603]
CT7  1uF/16V  [TANT-A]
CT8  1uF/10V  [C0805]
J3  Micro-USB 5-pin  [MICRO_USB_AB]
L6  FERRITE BEAD  [L0603]
L7  FERRITE BEAD  [L0603]
R28  200R 1%  [R0603]
R29  4.7K  [R0603]
R30  0  [R0603]
R31  10K  [R0603]
R32  0  [R0603]
U4  TPS2065CDBVR-2  [SOT23-5]
sheet Leds & Buttons
BTN0  3x6x5 2PIN SMD  [SW-2P-SMD]
BTN1  3x6x5 2PIN SMD  [SW-2P-SMD]
LED_PWR  0805 LED G (ºñ¥ú) ´¶«G  [LED0805]
LEDG  0805 LED G (ºñ¥ú) ´¶«G  [LED0805]
LEDR  0805 LED R (¬õ¥ú) °ª«G  [LED0805]
LEDY  0805 LED Y (¶À¥ú)°ª«G  [LED0805]
R78  330  [R0603]
R79  330  [R0603]
R80  330  [R0603]
R81  330  [R0603]
R82  10K  [R0603]
R83  10K  [R0603]
sheet M460_LQFP176
C1  0.1u  [C0603]
C2  10u  [C0603]
C3  0.1u  [C0603]
C4  1u  [C0603]
C5  0.1u  [C0603]
C6  1u  [C0603]
C7  0.1u  [C0603]
C8  0.1u  [C0603]
C9  1u  [C0603]
C10  0.1u  [C0603]
C11  20p  [C0603]
C12  1u  [C0603]
C13  0.1u  [C0603]
C14  0.1u  [C0603]
C15  0.1u  [C0603]
C16  20p  [C0603]
C17  20p  [C0603]
C18  0.01u  [C0603]
C19  0.1u  [C0603]
C20  0.01u  [C0603]
C21  1u  [C0603]
C22  0.1u  [C0603]
C23  20p  [C0603]
CT3  10uF/10V  [TANT-A]
CT4  10uF/10V  [TANT-A]
J1  HEADER5X2(NC)  [HEADER5X2]
L2  FERRITE BEAD  [L0603]
L3  FERRITE BEAD  [L0603]
L4  FERRITE BEAD  [L0603]
R3  NC  [R0603]
R4  NC  [R0603]
R5  10K  [R0603]
R6  0  [R0603]
R7  0  [R0603]
R8  0  [R0603]
R9  0  [R0603]
R10  0  [R0603]
R11  0  [R0603]
RESET  3x6x5 2PIN SMD  [SW-2P-SMD]
U1  M467HJHAN  [QFP176/26/0.5]
VBAT  NC  [HEADER2X1]
VDDIO  NC  [HEADER2X1]
VREF  NC  [HEADER2X1]
X1  12MHz SMD X3225B  [CRYSTAL_SMD]
X2  X3215 32.768KHz SMD  [9HT9]
sheet MikroBUS
MBUS0  HEADER 2.54 8x1 Female 2-Row  [MIKROBUS]
MBUS1  HEADER 2.54 8x1 Female 2-Row  [MIKROBUS]
sheet Nu-Link2-Me
ICEC1  0.1u  [C0603]
ICEC2  1u  [C0603]
ICEC3  1u  [C0603]
ICEC4  0.1u  [C0603]
ICEC5  0.1u  [C0603]
ICEC6  1u  [C0603]
ICEC7  4.7u  [C0603]
ICEC8  470p  [C0603]
ICEC9  1u  [C0603]
ICEC10  20p  [C0603]
ICEC11  20p  [C0603]
ICEC12  0.1u  [C0603]
ICECT1  10uF/10V  [TANT-A]
ICECT2  10uF/10V  [TANT-A]
ICECT3  10uF/10V  [TANT-A]
ICED1  SS24A  [RB060L]
ICED3  0.1u  [C0603]
ICED4  SS24A  [RB060L]
ICEJ1  HEADER_5(NC)  [HEADER5X1]
ICEJ2  HEADER04(NC)  [HEADER04]
ICEJ3  micro USB 5pin  [MICRO_USB_AB]
ICEJ4  HEADER 2.54 5X2 (NC)  [HEADER5X2]
ICEJPR1  1&2 (0 ohm)  [R0603X3]
ICEJPR2  1&2 (0 ohm)  [R0603X2]
ICEL1  FERRITE BEAD  [L0603]
ICEL2  FERRITE BEAD  [L0603]
ICER1  200 1%  [R0603]
ICER2  10K  [R0603]
ICER3  10K  [R0603]
ICER4  10K  [R0603]
ICER5  10K  [R0603]
ICER6  0  [R0603]
ICER7  0  [R0603]
ICER8  120,1%  [R0603]
ICER9  82, 1%  [R0603]
ICER18  10K  [R0603]
ICER19  10K  [R0603]
ICERP1  8P4R-330  [8P4RA]
ICES0  0805 LED R (¬õ¥ú) °ª«G  [KP-2012]
ICES1  0805 LED Y (¶À¥ú)°ª«G  [KP-2012]
ICES2  0805 LED R (¬õ¥ú) °ª«G  [KP-2012]
ICES3  0805 LED G (ºñ¥ú) ´¶«G  [KP-2012]
ICESW1  3x6x5 2PIN SMD  [SW-2P-SMD]
ICESW2  SMD HPS604-E  [SW1X4]
ICEU1  M48SSIDAE  [LQFP64_7x7_M48SSIDAE]
ICEU2  W25Q16JVSSIQ  [SOP8\5.23/1.27MM]
ICEU3  SN74LVC2T45DCUR  [SOP8/3.1/0.5]
ICEU4  SN74LVC2T45DCUR  [SOP8/3.1/0.5]
ICEUP1  AMS1117_3.3v  [SOT-223-1]
ICEUP2  ACE1117_ADJ  [SOT-223-1]
ICEX1  12MHz SMD X3225B  [CRYSTAL_SMD]
sheet Power Source
AMMETER  NC  [HEADER2X1]
CT1  10uF/10V  [TANT-A]
CT2  10uF/10V  [TANT-A]
D1  SS24A  [RB060L]
D2  SS24A  [RB060L]
D3  SS24A  [RB060L]
JP1  HEADER1X4(NC)  [header1x4]
JP2  HEADER1X4(NC)  [header1x4]
L1  FERRITE BEAD  [L0603]
R1  0  [R0603]
R2  0  [R0603]
UP1  AMS1117_5v  [SOT-223-1]
UP2  AMS1117_3.3v  [SOT-223-1]
sheet SD Card
C32  0.1u  [C0603]
C33  0.1u  [C0603]
L8  FERRITE BEAD  [L0603]
R33  330  [R0603]
RP1  8P4R-10K  [8P4RA]
RP2  8P4R-10K  [8P4RA]
SD_PWR  0805 LED G (ºñ¥ú) ´¶«G  [LED0805]
U5  T-Flash Card  [B8502A-13SB-HPA]
sheet SPI Flash
C25  0.1u  [C0603]
R12  NC  [R0603]
R13  0  [R0603]
R14  NC  [R0603]
R15  0  [R0603]
R16  NC  [R0603]
R17  0  [R0603]
R18  NC  [R0603]
R19  0  [R0603]
R20  NC  [R0603]
R21  0  [R0603]
R22  NC  [R0603]
R23  0  [R0603]
U11  W25Q32JVSSIQ  [SOP8\5.23/1.27MM]
sheet Thermal Sensor
C78  0.1u  [C0603]
R84  4.7K  [R0603]
R85  4.7K  [R0603]
U10  NCT7717U
sheet UNO I/F
NU1  HEADER8X1 (2.54mm, female, top)  [SIP-8P]
NU2  HEADER10X1 (2.54mm, female, top)  [SIP-10P]
NU3  HEADER6X1(2.54mm, female, top)  [SIP-6P]
NU4  HEADER8X1 (2.54mm, female, top)  [SIP-8P]
NU5  HEADER2X4(2.54mm, male, top)  [HEADER4X2]
sheet WiFi Module
C38  0.1u  [C0603]
R60  10KR  [R0603]
R61  10KR  [R0603]
R62  10KR  [R0603]
R63  10KR  [R0603]
R64  10KR  [R0603]
SW5  SMD HPS602-E  [SW1X2]
U9  ESP-12  [ESP-12F_MODULE]

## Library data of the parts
C24 C34 C35 = CAPACITOR_NP: Mount: M; Part Number: 880600286
R65 = RES: CHIP RES 33 J 1/16W 0402; AssemblyLevel: SMT; FPLIST: AGPR0402,R0402; Manufacturer: YAGEO; Manufacturer's Part Number: RC0402JR-0733RL; Package Type: 0402; Part Number: 6C.33034.1D1; TempSpec1: http://qtyncr.qisda.qcorp.com/egim/spfile/egimspectxtSpecFile1AAAAAAAA20041195466994309734382.pdf; facility: TF; specdesc: CHIP RES 33 J 1/16W 0402
U12 = MPU6881
C22 C25 C27 C30 C32 C39 C58 C78 = C_0.1u: element_no: C0004
C15 C26 C29 C33 C40 C41 = C_0.1u_1: element_no: C0004
C18 C31 C49 C60 = C_0.1u_2: element_no: C0004
J8 = HEADER_2
R1 R10 R21 R25 R29 R34 R52 R84 = R_0_1
R3 R19 R27 R30 R35 R38 = R_0_2
R2 R5 R23 R24 R28 R33 R36 R45 R85 = R_0
U6 = TCAN332GD_1
C11 C42 = C_0.1u_8: element_no: C0004
C3 C43 = C_0.1u_6: element_no: C0004
C5 C44 = C_0.1u_5: element_no: C0004
C13 C28 C45 = C_0.1u_3: element_no: C0004
C21 C46 = C_0.1u_18: element_no: C0004
C9 C47 = C_0.1u_14: element_no: C0004
C16 C48 = C_0.1u_10: element_no: C0004
C23 C50 = C_0.1u_15: element_no: C0004
C1 C51 = C_0.1u_13: element_no: C0004
C10 C52 = C_0.1u_11: element_no: C0004
C20 C53 = C_0.1u_12: element_no: C0004
C12 C54 = C_0.1u_9: element_no: C0004
C14 C55 = C_0.1u_16: element_no: C0004
C19 C56 = C_0.1u_17: element_no: C0004
C7 C57 = C_0.1u_7: element_no: C0004
C4 C59 = C_0.1u_4: element_no: C0004
CON3 = RJ45_SHLD_2
ICEL1 L1 L2 L5 L7-L9 = FERRITE_BEAD
R6 R15 R37 = R_0_6
R39 = R_0_16
R11 R16 R40 = R_0_7
R41 = R_0_13
R42 = R_0_12
R22 R43 = R_0_11
R8 R20 R26 R31 R44 = R_0_3
R46 = R_0_18
R7 R14 R47 = R_0_8
R9 R18 R32 R48 = R_0_4
R13 R49 = R_0_9
R50 = R_0_15
R51 = R_0_17
R4 R17 R53 = R_0_5
R54 = R_1
R55 = R_0_14
R56 = R_2
R57 = R_3
R58 = R
R12 R59 = R_0_10
U7 = RTL8201FI-VC
U8 = PE-68515_0
X3 = Crystal_SMD_2: Vendor: Aurum
CT1-CT8 ICECT1-ICECT3 = C_10uF_10V
ICEJ3 J2 J3 = micro_USB_5pin_0
U3 U4 = NCT3520U
ICEL2 L4 L6 = FERRITE_BEAD_1
BTN0 ICESW1 RESET = SW_PUSHBUTTON_0
BTN1 = SW_PUSHBUTTON_0_1
LED_PWR = LED_0_1: Package: KP-2012; Vendor: Kingbright
LEDG = LED_0_3: Package: KP-2012; Vendor: Kingbright
LEDR SD_PWR = LED_0: Package: KP-2012; Vendor: Kingbright
LEDY = LED_0_2: Package: KP-2012; Vendor: Kingbright
ICER5 R78 = R_0_5: Package: 0603
ICER4 R79 = R_0_4: Package: 0603
ICER1 R80 = R_0: Package: 0603
ICER9 R81 = R_0_2: Package: 0603
ICER19 R82 = R_0_1: Package: 0603
ICER2 R83 = R_0_3: Package: 0603
C2 = C_0.1u_19: element_no: C0004
C6 = C_0.1u_21: element_no: C0004
C8 = C_0.1u_20: element_no: C0004
C17 = C_0.1u_22: element_no: C0004
ICEJ4 J1 = HEADER_5X2
L3 = FERRITE_BEAD_2
U1 = M460_LQFP176
VBAT = HEADER_2_v2_2
AMMETER VDDIO = HEADER_2_v2
VREF = HEADER_2_v2_1
X1 = Crystal_SMD_2
X2 = MA306_SM_1
MBUS0 MBUS1 = MikroBUS_2
ICEC1 = CAP-C_10: Package: 0603; element_no: C0004
ICEC2 = CAP-C_12: Package: 0603; element_no: C0006
ICEC3 = CAP-C_4: Package: 0603; element_no: C0006
ICEC4 = CAP-C_6: Package: 0603; element_no: C0004
ICEC5 = CAP-C_3: Package: 0603; element_no: C0004
ICEC6 = CAP-C_11: Package: 0603; element_no: C0006
ICEC7 = CAP-C_8: Package: 0603
ICEC8 = CAP-C_2: Package: 0603
ICEC9 = CAP-C: Package: 0603; element_no: C0006
ICEC10 = CAP-C_5: Package: 0603
ICEC11 = CAP-C_7: Package: 0603
ICEC12 = CAP-C_9: Package: 0603; element_no: C0004
D2 ICED1 = D_SS24A
ICED3 = CAP-C_1: Package: 0603; element_no: C0004
D1 ICED4 = D_SS24A_1
ICEJ1 = HEADER_5
ICEJ2 = HEADER_4
ICEJPR1 = HEADER_3_0
ICEJPR2 = HEADER_3
ICER3 = R_0_6: Package: 0603
ICER6 = R_33_1
ICER7 = R_33
ICER8 = R_0_8: Package: 0603
ICER18 = R_0_7: Package: 0603
ICERP1 RP1 RP2 = R-PACK8_0
ICES0 = LED_0_1: Vendor: Kingbright
ICES1 = LED_0: Vendor: Kingbright
ICES2 = LED_0_3: Vendor: Kingbright
ICES3 = LED_0_2: Vendor: Kingbright
ICESW2 = SW_DIP-4_SM
ICEU1 = M487SIDAE_0: M487SIDAE: <M48SSIDAE>
ICEU2 U11 = W25P10_20_40_SOIC_0: Package: SOP8; Vendor: WINBOND
ICEU3 ICEU4 = SN74LV2T45
ICEUP1 UP1 UP2 = TO-247_Regulator_10
ICEUP2 = TO-247_Regulator_0
ICEX1 = Crystal_SMD_1
D3 = D_SS24A_2
JP1 JP2 = HEADER_4_v2
U5 = B8502A-13SB-HPA_(T-Flash_Card)
U10 = NCT7717U
NU1 = POWER_CONNECT_0
NU2 = PWM1_CONNECT_1
NU3 = ADC_CONNECT_0
NU4 = PWM0_CONNECT_0
NU5 = NuEdu_NU7
C38 = C_0.1u
R60 = R_100_3
R61 = R_100_1
R62 = R_100_2
R63 = R_100
R64 = R_100_4
SW5 = SW_DIP-4_2
U9 = ESP-12

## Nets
1.8V: ICECT3.1 ICEJPR1.3 ICEJPR2.3 ICER8.1 ICEUP2.2(OUT) ICEUP2.4(OUT)
3.3V: ICEC1.1 ICEC12.1 ICECT1.1 ICEJPR1.1 ICEJPR2.1 ICER18.2 ICER19.2 ICEU1.42(HSUSB_VDD33) ICEU2.8(VCC) ICEU3.1(VCCA) ICEU4.1(VCCA) ICEUP1.2(OUT) ICEUP1.4(OUT)
AVDD: C19.1 C20.1 CT4.1 L2.1 L3.2 U1.168(AVDD) VREF.1
AVDD10: C49.2 U7.2(AVDD10OUT)
AVSS: C12.2 C13.2 C19.2 C20.2 CT4.2 L4.2 U1.170(AVSS)
DVDD10: C43.2 U7.29(DVDD10OUT)
GND: BTN0.1 BTN1.1 C1.2 C2.2 C3.2 C4.2 C5.2 C6.2 C7.2 C8.2 C9.2 C10.2 C11.1 C14.2 C15.2 C16.1 C17.2 C18.2 C21.2 C22.2 C23.2 C24.2 C25.2 C26.2 C27.2 C30.2 C31.2 C32.2 C33.2 C34.2 C35.2 C38.2 C39.2 C40.2 C41.2 C42.2 C43.1 C44.2 C45.2 C46.2 C47.1 C48.2 C49.1 C50.2 C51.2 C52.2 C53.2 C54.2 C56.2 C57.2 C58.2 C59.2 C60.2 C78.2 CT1.2 CT2.2 CT3.2 CT5.2 CT6.2 CT7.2 CT8.2 ICEC1.2 ICEC2.2 ICEC3.2 ICEC4.2 ICEC5.2 ICEC6.2 ICEC7.1 ICEC8.1 ICEC9.1 ICEC10.1 ICEC11.1 ICEC12.2 ICECT1.2 ICECT2.2 ICECT3.2 ICED3.1 ICEJ1.5 ICEJ2.4 ICEJ3.5(GND) ICEJ4.9 ICEL2.1 ICER1.2 ICER9.1 ICESW1.1 ICESW2.4(A4) ICEU1.6(PB.1) ICEU1.7(PB.0) ICEU1.22(VSS) ICEU1.45(HSUSB_VSS) ICEU1.49(VSS) ICEU1.59(AVSS) ICEU2.4(GND) ICEU3.4(GND) ICEU3.5(DIR) ICEU4.4(GND) ICEU4.5(DIR) ICEUP1.1(GND) ICEX1.2(GND) ICEX1.4(GND) J1.10 J2.5(GND) J3.5(GND) JP2.1 JP2.2 JP2.3 JP2.4 L4.1 L5.1 L6.2 L7.1 LED_PWR.2 MBUS0.8(GND) MBUS0.9(GND) MBUS1.8(GND) MBUS1.9(GND) NU1.6(VSS) NU1.7(VSS) NU2.7(VSS) NU5.6(GND) R26.1 R31.1 R37.2 R41.2 R42.2 R48.2 R54.2 R58.1 R63.2 RESET.2 SD_PWR.2 SW5.2(A2) U1.11(VSS) U1.21(VSS) U1.53(VSS) U1.72(VSS) U1.95(VSS) U1.141(VSS) U1.160(VSS) U3.2(GND) U4.2(GND) U5.6(VSS) U5.10(GND) U5.11(GND) U5.12(GND) U5.13(GND) U6.2(GND) U7.33(E_PAD) U9.15(GND) U10.2(GND) U11.4(GND) U12.9(SDO/AD0) U12.11(FSYNC) U12.18(GND) U12.19(RESV) UP1.1(GND) UP2.1(GND) X1.2(GND) X1.4(GND) X3.2(GND) X3.4(GND)
GND_EARTH: C41.1 C42.1 C44.1 C45.1 C48.1 C55.2 CON3.13(Shield) CON3.14(Shield)
VBAT: C21.1 C22.1 R9.2 U1.40(VBAT) VBAT.2
VDD3V3: C46.1 L9.2 R38.2 R39.2
VDD_MCU: AMMETER.2 C1.1 C5.1 C7.1 C8.1 C10.1 C14.1 C15.1 C18.1 CT3.1 L3.1 R1.2 R5.2 R6.2 R9.1 U1.12(VDD) U1.22(VDD) U1.54(VDD) U1.73(VDD) U1.96(VDD) U1.142(VDD) U1.162(VDD) VBAT.1 VDDIO.2
VDDIO: C3.1 C4.1 R6.1 U1.81(VDDIO) VDDIO.1
BTN_0: BTN0.2 R82.2 U1.43(PH0)
BTN_1: BTN1.2 R83.2 U1.44(PH1)
BUSY: ICEJ4.2 ICEU1.27(PA.3) ICEU1.56(PB.12)
CAN0_H: J8.1 R35.2 U6.7(CANH)
CAN0_L: J8.2 R35.1 U6.6(CANL)
CAN-FD_RX: U1.153(PJ11) U6.4(RXD)
CAN-FD_TX: U1.152(PJ10) U6.1(TXD)
CLK: R14.1 R15.1 U11.6(CLK)
COM_RX: ICEJ4.10 ICESW2.2(A2) J1.9 U1.167(PB12)
COM_TX: ICEJ4.8 ICESW2.1(A1) J1.7 U1.166(PB13)
CS: R12.1 R13.1 U11.1(CS#)
DM: ICEJ2.2 ICEJ3.2(D-) ICER6.2
DP: ICEJ2.3 ICEJ3.3(D+) ICER7.2
ETH_XI: C58.1 R59.2 U7.31(CKXTAL1) X3.1(XIN)
ETH_XO: C59.1 R59.1 U7.32(CKXTAL2) X3.3(XOUT)
ETMD1: ICEU1.54(PB.14)
ETMD2_CK: ICEJ4.4 ICEU1.28(PA.2) ICEU1.55(PB.13)
FLASH_CLK: R14.2 R19.2 U1.70(PJ0)
FLASH_IO2: R13.2 R20.2 U1.68(PI14)
FLASH_IO3: R15.2 R22.2 U1.69(PI15)
FLASH_MISO: R18.2 R21.2 U1.67(PI13)
FLASH_MOSI: R16.2 R17.2 U1.71(PJ1)
FLASH_nCS: R12.2 R23.2 U1.66(PI12)
FSUSB_D+: R27.2 U1.125(PA14)
FSUSB_D-: R25.2 U1.124(PA13)
FSUSB_ID: J2.4(ID) U1.126(PA15)
FSUSB_VBUS: C26.1 CT5.1 D2.1 J2.1(VBUS) U1.123(PA12) U3.1(OUT)
FSUSB_VBUS_EN: R26.2 U1.164(PB15) U3.4(EN/EN#)
FSUSB_VBUS_ST: R24.1 U1.163(PC14) U3.3(OC#)
GREEN: ICES3.2 ICEU1.63(PB.8)
HSUSB_D+: R32.2 U1.132(HSUSB_D+)
HSUSB_D-: R30.2 U1.130(HSUSB_D-)
HSUSB_ID: J3.4(ID) U1.134(HSUSB_ID)
HSUSB_VBUS: C30.1 CT7.1 D3.1 J3.1(VBUS) U1.129(HSUSB_VBUS) U4.1(OUT)
HSUSB_VBUS_EN: R31.2 U1.155(PJ13) U4.4(EN/EN#)
HSUSB_VBUS_ST: R29.1 U1.154(PJ12) U4.3(OC#)
HSUSB_VDD12_CAP: C28.1 U1.133(HSUSB_VDD12_CAP)
HSUSB_VRES: R28.2 U1.127(HSUSB_VRES)
HSUSB_VSS: C28.2 C29.2 L6.1 R28.1 U1.131(HSUSB_VSS)
HXT_I: ICEC11.2 ICEU1.16(PF.3) ICEX1.1(XIN)
HXT_O: ICEC10.2 ICEU1.17(PF.2) ICEX1.3(XOUT)
I2C2_SCL: R84.1 U1.120(PD1) U10.1(SCL) U12.23(SCL/SCLK)
I2C2_SDA: R85.1 U1.121(PD0) U10.5(SDA) U12.24(SDA/SDI)
ICE5V: ICED1.2 ICEJPR1.4 ICEUP1.3(IN) ICEUP2.3(IN) L1.1
ICE_CLK: ICEJ1.3 ICER4.1 ICEU1.34(PF.1)
ICE_DAT: ICEJ1.2 ICER2.1 ICEU1.33(PF.0)
ICE_RST: ICEC9.2 ICEJ1.4 ICER3.2 ICEU1.32(nRESET)
ICE_RX: ICESW2.8(B1) ICEU1.30(PA.0) ICEU1.52(PC.14)
ICE_TX: ICESW2.7(B2) ICEU1.29(PA.1) ICEU1.53(PB.15)
ICELED: ICES0.2 ICEU1.15(PF.4)
ICEVCC: ICEJPR2.2 ICEL1.1
ICEVDD: ICEC4.1 ICEC5.1 ICEC7.2 ICEC8.2 ICECT2.1 ICEJ1.1 ICEL1.2 ICER2.2 ICER3.1 ICER4.2 ICER5.2 ICERP1.1(R1) ICERP1.3(R2) ICERP1.5(R3) ICERP1.7(R4) ICEU1.13(VBAT) ICEU1.23(VDD) ICEU1.31(VDDIO) ICEU1.51(VDD) ICEU1.57(AVDD) ICEU1.58(VREF) ICEU3.8(VCCB) ICEU4.8(VCCB)
IO2: R20.1 R21.1 U11.3(WP#)
IO3: R22.1 R23.1 U11.7(HOLD#)
ISPLED: ICES1.2 ICEU1.19(PC.6)
KEY1: ICER5.1 ICESW1.2 ICEU1.18(PC.7)
LDO_3_3V: CT2.1 NU1.4(3VCC) R2.1 UP2.2(OUT) UP2.4(OUT)
LDO_5V: C27.1 C31.1 CT6.1 CT8.1 D1.2 D2.2 D3.2 L1.2 MBUS0.10(+5V) MBUS1.10(+5V) NU1.5(5VCC) U3.5(IN) U4.5(IN) UP2.3(IN)
LDO_CAP1: C6.1 U1.74(LDO_CAP)
LDO_CAP2: C9.1 U1.161(LDO_CAP)
LED0: C51.1 R40.2 R46.2 U7.24(LED0/PHYAD[0]/PMEB)
LED1: C50.1 R41.1 R47.2 U7.25(LED1/PHYAD[1])
LED_G: LEDG.2 U1.49(PH6)
LED_R: LEDR.2 U1.47(PH4)
LED_Y: LEDY.2 U1.48(PH5)
M_SENSOR_INT: R65.2 U1.119(PD2) U12.12(INT)
MBUS0_AN: MBUS0.1(AN) U1.19(PD11)
MBUS0_CLK: MBUS0.4(SCK) U1.31(PI9)
MBUS0_INT: MBUS0.15(INT) U1.100(PG12)
MBUS0_MISO: MBUS0.5(MISO) U1.29(PI7)
MBUS0_MOSI: MBUS0.6(MOSI) U1.30(PI8)
MBUS0_PWM: MBUS0.16(PWM) U1.148(PH11)
MBUS0_RST: MBUS0.2(RST) U1.99(PG11)
MBUS0_RXD: MBUS0.14(RX) U1.35(PF10)
MBUS0_SCL: MBUS0.12(SCL) U1.25(PG2)
MBUS0_SDA: MBUS0.11(SDA) U1.26(PG3)
MBUS0_SS: MBUS0.3(CS) U1.32(PI10)
MBUS0_TXD: MBUS0.13(TX) U1.34(PF11)
MBUS1_AN: MBUS1.1(AN) U1.20(PD10)
MBUS1_CLK: MBUS1.4(SCK) U1.157(PG6)
MBUS1_INT: MBUS1.15(INT) U1.102(PG14)
MBUS1_MISO: MBUS1.5(MISO) U1.158(PG7)
MBUS1_MOSI: MBUS1.6(MOSI) U1.159(PG8)
MBUS1_PWM: MBUS1.16(PWM) U1.149(PD14)
MBUS1_RST: MBUS1.2(RST) U1.101(PG13)
MBUS1_RXD: MBUS1.14(RX) U1.39(PF6)
MBUS1_SCL: MBUS1.12(SCL) U1.97(PG9)
MBUS1_SDA: MBUS1.11(SDA) U1.98(PG10)
MBUS1_SS: MBUS1.3(CS) U1.156(PG5)
MBUS1_TXD: MBUS1.13(TX) U1.38(PF7)
MCUVCC: ICED4.1 ICEJPR1.2
MCUVCC_DIODE: AMMETER.1 C25.1 C29.1 C32.1 C34.1 C35.1 C38.1 C78.1 ICED4.2 ICEJ4.1 J1.2 JP1.1 JP1.2 JP1.3 JP1.4 L8.1 L9.1 MBUS0.7(+3.3V) MBUS1.7(+3.3V) NU1.2(VDD) NU5.2(VCC) R1.1 R2.2 R3.2 R4.2 R24.2 R29.2 R34.2 R36.1 R60.1 R61.1 R62.1 R64.1 R65.1 R78.1 R79.1 R80.1 R81.1 R82.1 R83.1 R84.2 R85.2 RP1.2(R1) RP1.4(R2) RP1.6(R3) RP1.8(R4) RP2.2(R1) RP2.4(R2) RP2.6(R3) RP2.8(R4) U1.128(HSUSB_VDD33) U9.8(VCC) U10.4(VDD) U11.8(VCC) U12.8(VDDIO) U12.13(VDD) U12.22(nCS)
MDI0+: U7.3(MDI+[0]) U8.8(RD-)
MDI0-: U7.4(MDI-[0]) U8.6(RD+)
MDI1+: U7.5(MDI+[1]) U8.3(TD-)
MDI1-: U7.6(MDI-[1]) U8.1(TD+)
MISO: R18.1 R19.1 U11.2(DO)
MOSI: R16.1 R17.1 U11.5(DI)
MSG_EN: ICESW2.5(B4) ICEU1.12(PF.6)
PB10: U1.172(PB10)
PB11: U1.171(PB11)
PB14: U1.165(PB14)
PC5: U1.89(PC5)
PD3: U1.118(PD3)
PD4: U1.117(PD4)
PD5: U1.116(PD5)
PD6: U1.115(PD6)
PD7: U1.114(PD7)
PD8: U1.88(PD9)
PD9: U1.87(PD8)
PD12: U1.18(PD12)
PE0: U1.144(PE0)
PE1: U1.143(PE1)
PE13: U1.60(PE13)
PE14: U1.82(PE14)
PE15: U1.83(PE15)
PF8: U1.37(PF8)
PF9: U1.36(PF9)
PG4: U1.27(PG4)
PG15: U1.103(PG15)
PH2: U1.45(PH2)
PH3: U1.46(PH3)
PH7: U1.50(PH7)
PH8: U1.145(PH8)
PH9: U1.146(PH9)
PH10: U1.147(PH10)
PH12: U1.110(PH12)
PH13: U1.111(PH13)
PH14: U1.112(PH14)
PH15: U1.113(PH15)
PHY_AVDD3V3: C47.2 C52.1 R38.1 U7.7(AVDD33) U7.30(AVDD33)
PHY_VDD3V3: C56.1 R39.1 R40.1 R43.2 R44.2 R45.2 R49.1 R56.2 R57.2 U7.14(DVDD33)
PI6: U1.28(PI6)
PI11: U1.33(PI11)
PJ2: U1.104(PJ2)
PJ3: U1.105(PJ3)
PJ4: U1.106(PJ4)
PJ5: U1.107(PJ5)
PJ6: U1.108(PJ6)
PJ7: U1.109(PJ7)
PJ8: U1.150(PJ8)
PJ9: U1.151(PJ9)
RED: ICES2.2 ICEU1.62(PB.9)
RMII_MDC: U1.55(PE8) U7.22(MDC)
RMII_MDIO: R44.1 U1.56(PE9) U7.23(MDIO)
RMII_REFCLK: C57.1 R55.1 U1.61(PC8)
RMII_RXD0: U1.62(PC7) U7.9(RXD[0])
RMII_RXD1: R54.1 U1.63(PC6) U7.10(RXD[1])
RMII_RXDV: U1.64(PA7) U7.26(CRS/CRS_DV)
RMII_RXERR: R37.1 U1.65(PA6) U7.28(RXER/FXEN)
RMII_TXD0: U1.57(PE10) U7.16(TXD[0])
RMII_TXD1: U1.58(PE11) U7.17(TXD[1])
RMII_TXEN: U1.59(PE12) U7.20(TXEN)
RX+: CON3.3(DB+) U8.14(TX-)
RX-: CON3.6(DB-) U8.16(TX+)
RXD2/INTB: R56.1 U7.11(RXD[2]/INTB)
RXD3: R57.1 R58.2 U7.12(RXD[3]/CLK_CTL)
SDHC_CLK: U1.136(PE6) U5.5(CLK)
SDHC_CMD: RP2.1(R1) U1.135(PE7) U5.3(CMD)
SDHC_DAT0: RP1.7(R4) U1.140(PE2) U5.7(DAT0)
SDHC_DAT1: RP1.5(R3) U1.139(PE3) U5.8(DAT1)
SDHC_DAT2: RP2.5(R3) U1.138(PE4) U5.1(DAT2)
SDHC_DAT3: RP2.3(R2) U1.137(PE5) U5.2(DAT3)
SDHC_nCS: RP1.3(R2) U1.122(PD13) U5.9(CD)
SPIM_CLK: ICEU1.38(PC.2) ICEU4.7(B1)
SPIM_CLK_LV: ICEU2.6(CLK) ICEU4.2(A1)
SPIM_CS: ICEU1.37(PC.3) ICEU3.7(B1)
SPIM_CS_LV: ICEU2.1(CS#) ICEU3.2(A1)
SPIM_D2: ICEU1.35(PC.5)
SPIM_D3: ICEU1.36(PC.4)
SPIM_MISO0: ICEU1.39(PC.1) ICEU2.2(DO)
SPIM_MOSI0: ICEU1.40(PC.0) ICEU4.6(B2)
SPIM_MOSI0_LV: ICEU2.5(DI) ICEU4.3(A2)
SWO: ICEJ4.6 ICEU1.26(PA.4)
TICECLK: ICEJ4.5 ICEU1.9(PA.10) J1.6 R4.1 U1.86(PF1)
TICEDAT: ICEJ4.3 ICEU1.10(PA.9) J1.4 R3.1 U1.85(PF0)
TICERST: C2.1 ICEJ4.7 ICEU1.14(PF.5) J1.8 NU1.3(MCU_RESET) NU5.5(RESET) R5.1 R45.1 RESET.1 U1.84(nRESET) U7.21(PHYRSTB)
TX+: CON3.1(DA+) U8.9(RX-)
TX-: CON3.2(DA-) U8.11(RX+)
TXC: R55.2 U7.15(TXC)
UNO_A0: NU3.1(A0) U1.176(PB6)
UNO_A1: NU3.2(A1) U1.175(PB7)
UNO_A2: NU3.3(A2) U1.174(PB8)
UNO_A3: NU3.4(A3) U1.173(PB9)
UNO_A4: NU3.5(A4/SDA) U1.10(PB0)
UNO_A5: NU3.6(A5/SCL) U1.9(PB1)
UNO_CLK: NU5.3(SPI0_CLK) U1.14(PA10)
UNO_D0: NU4.1(D0) U1.4(PB2)
UNO_D1: NU4.2(D1) U1.3(PB3)
UNO_D2: NU4.3(D2) U1.8(PC9)
UNO_D3: NU4.4(D3) U1.7(PC10)
UNO_D4: NU4.5(D4) U1.6(PC11)
UNO_D5: NU4.6(D5) U1.5(PC12)
UNO_D6: NU4.7(D6) U1.2(PB4)
UNO_D7: NU4.8(D7) U1.1(PB5)
UNO_D8: NU2.1(D8) U1.75(PA5)
UNO_D9: NU2.2(D9) U1.76(PA4)
UNO_D10: NU2.3(D10) U1.77(PA3)
UNO_D11: NU2.4(D11) U1.80(PA0)
UNO_D12: NU2.5(D12) U1.79(PA1)
UNO_D13: NU2.6(D13) U1.78(PA2)
UNO_IO: NU5.8(GPIO) U1.17(PC13)
UNO_MISO: NU5.1(SPI0_MISO) U1.15(PA9)
UNO_MOSI: NU5.4(SPI0_MOSI) U1.16(PA8)
UNO_SCL: NU2.10(I2C_SCL) U1.23(PG0)
UNO_SDA: NU2.9(I2C_SDA) U1.24(PG1)
UNO_SS: NU5.7(SPI0_SS) U1.13(PA11)
UNO_VIN: CT1.1 NU1.8(VIN) UP1.3(IN)
USB_HS_CAP: ICEC2.1 ICEU1.47(HSUSB_VDD12_CAP)
USB_HS_D+: ICER7.1 ICEU1.46(HSUSB_D+)
USB_HS_D-: ICER6.1 ICEU1.44(HSUSB_D-)
USB_HS_REXT: ICER1.1 ICEU1.41(HSUSB_VRES)
USB_HS_VBUS: ICED1.1 ICED3.2 ICEJ2.1 ICEJ3.1(VBUS) ICEU1.43(HSUSB_VBUS)
VREF: C12.1 C13.1 L2.2 NU2.8(VREF) U1.169(VREF) VREF.2
WFIF_RST: R60.2 U1.90(PC4) U9.1(RST)
WiFi_IO0: R64.2 SW5.3(B1) U9.18(IO0)
WIFI_nCTS: U1.91(PC3) U9.7(IO13)
WIFI_nRTS: R63.1 U1.92(PC2) U9.16(IO15)
WIFI_RXD: U1.94(PC0) U9.22(TXD)
WIFI_TXD: U1.93(PC1) U9.21(RXD)
X32_IN: R11.1 U1.41(PF5)
X32_OUT: R10.1 U1.42(PF4)
XT_IN: R7.2 U1.51(PF3)
XT_OUT: R8.2 U1.52(PF2)
N131550: C11.2 R7.1 X1.1(XIN)
N131573: C16.2 R8.1 X1.3(XOUT)
N136158: C17.1 R10.2 X2.2
N136165: C23.1 R11.2 X2.1
N171870: ICEC6.1 ICEU1.24(LDO_CAP)
N172066: ICEC3.1 ICEU1.50(LDO_CAP)
N173206: ICER18.1 ICEU2.7(HOLD#)
N173210: ICER19.1 ICEU2.3(WP#)
N173578: ICEJ3.6(Shield) ICEJ3.7(Shield) ICEJ3.8(Shield) ICEJ3.9(Shield) ICEJ3.10(Shield) ICEJ3.11(Shield) ICEL2.2
N173928: ICERP1.8(R4) ICES3.1
N173932: ICERP1.6(R3) ICES2.1
N174000: ICERP1.4(R2) ICES1.1
N174012: ICERP1.2(R1) ICES0.1
N174306: ICER8.2 ICER9.2 ICEUP2.1(ADJ)
N191363: D1.1 UP1.2(OUT) UP1.4(OUT)
N205391: J2.6(Shield) J2.7(Shield) J2.8(Shield) J2.9(Shield) J2.10(Shield) J2.11(Shield) L5.2
N205708: J2.2(D-) R25.1
N205723: J2.3(D+) R27.1
N213262: J3.6(Shield) J3.7(Shield) J3.8(Shield) J3.9(Shield) J3.10(Shield) J3.11(Shield) L7.2
N213428: J3.2(D-) R30.1
N213440: J3.3(D+) R32.1
N220222: C33.1 L8.2 R33.1 U5.4(VDD)
N220681: R33.2 SD_PWR.1
N16783286: C54.1 U8.7(CT)
N16783290: R52.1 U8.15(CT)
N16783302: R53.1 U8.10(CT)
N16783304: CON3.7(DD+) CON3.8(DD-) R50.1
N16783312: CON3.4(DC+) CON3.5(DC-) R51.1
N16783358: C53.1 U8.2(CT)
N16783537: CON3.9(LED-) R46.1
N16783550: CON3.12(LED+) R47.1
N16783556: CON3.10(LED+) R43.1
N16783580: CON3.11(LED-) R48.1
N16783676: R42.1 U7.1(RSET)
N16783698: R49.2 U7.8(RXDV)
N16831534: C55.1 R50.2 R51.2 R52.2 R53.2
N16841066: LEDR.1 R79.2
N16841068: LEDY.1 R80.2
N16841095: LEDG.1 R81.2
N16848964: LED_PWR.1 R78.2
N16960103: R61.2 U9.17(IO2)
N16960133: R62.2 U9.3(EN)
N16967994: C60.1 R36.2 U6.5(FAULT)
N16968008: C39.1 C40.1 R34.1 U6.3(VCC)
N16968410: C24.1 U12.10(REGOUT)

Not connected (* = marked no-connect by the designer): ICEJ3 4(ID)*; ICESW2 3(A3)* 6(B3)*; ICEU1 1(PB.6)* 2(PB.5)* 3(PB.4)* 4(PB.3)* 5(PB.2)* 8(PA.11)* 11(PA.8)* 20(PA.7)* 21(PA.6)* 25(PA.5)* 48(HSUSB_ID)* 60(PB.11)* 61(PB.10)* 64(PB.7)*; ICEU3 3(A2)* 6(B2)*; J1 1* 3* 5*; NU1 1(NC)*; RP1 1(R1)*; RP2 7(R4)*; SW5 1(A1)* 4(B2)*; U6 8(S)*; U7 13(RXC)* 18(TXD[2])* 19(TXD[3])* 27(COL); U8 4(NC)* 5(NC)* 12(NC)* 13(NC)*; U9 2(ADC)* 4(IO16)* 5(IO14)* 6(IO12)* 9(CS0)* 10(MISO)* 11(IO9)* 12(IO10)* 13(MOSI)* 14(SCLK)* 19(IO4)* 20(IO5)*; U10 3(ALERT#)*; U12 1(NC)* 2(NC)* 3(NC)* 4(NC)* 5(NC)* 6(NC)* 7(AUX_CL)* 14(NC)* 15(NC)* 16(NC)* 17(NC)* 20(RESV)* 21(AUX_DA)*

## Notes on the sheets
sheet 1
- Off-page Connector
- DEBUG
- RESET
- SPI FLASH
- Nu-Trace,   ID0 = 1, ID1 = 1
  Nu-Link2,   ID0 = 0, ID1 = 1
  Nu-LInk2-Me, ID0 = 0, ID1 = 0
- NULINK ID
- KEY
- Power Switch
- VCOM SWITCH
- 12M Crystal
- USB 2.0 HIGH SPEED DEVICES
- LED
- ICE INTERFACE
sheet 2
- Power Source
  5V
- Power Source
  MCU
- Power Source
  3.3V
sheet 3
- BYP
  CAP
- ICE SWD &
  Debug Port
- RESET
- VDDIO
- BYP
  CAP
- LDO
  CAP
- BYP
  CAP
- LDO
  CAP
- BYP
  CAP
- BYP
  CAP
- HXT
- BYP
  CAP
- BYP
  CAP
- VREF
- LXT
- AVDD
- VBAT
sheet 4
- off-Page
  Singals
- SPIM / QSPI
  Selection
- These resistors are
  used to determine
  the SPI Flash is
  controlled by which
  i/f. By default,
  it's controlled by
  SPIM.
sheet 5
- off-Page
  Singals
sheet 6
- off-Page
  Singals
sheet 7
- off-Page
  Singals
sheet 8
- off-Page
  Singals
sheet 9
- PHY Address 1 :2'b01
- off-Page
  Singals
sheet 10
- The 6-axis motion sensor (MPU6500) and
  thermal sensor (NCT7717U) are shared
  with  the  same I2C bus (I2C2)
- off-Page
  Singals
sheet 11
- off-Page
  Singals
- Buttons
- LEDs
sheet 12
- off-Page
  Singals
- ESP-12 WiFi Module
- FW Update
sheet 13
- off-Page
  Singals
- off-Page
  Singals
sheet 14
- off-Page
  Singals
sheet 15
- The 6-axis motion sensor (MPU6500) and
  thermal sensor (NCT7717U) are shared
  with  the  same I2C bus (I2C2)
- off-Page
  Singals
